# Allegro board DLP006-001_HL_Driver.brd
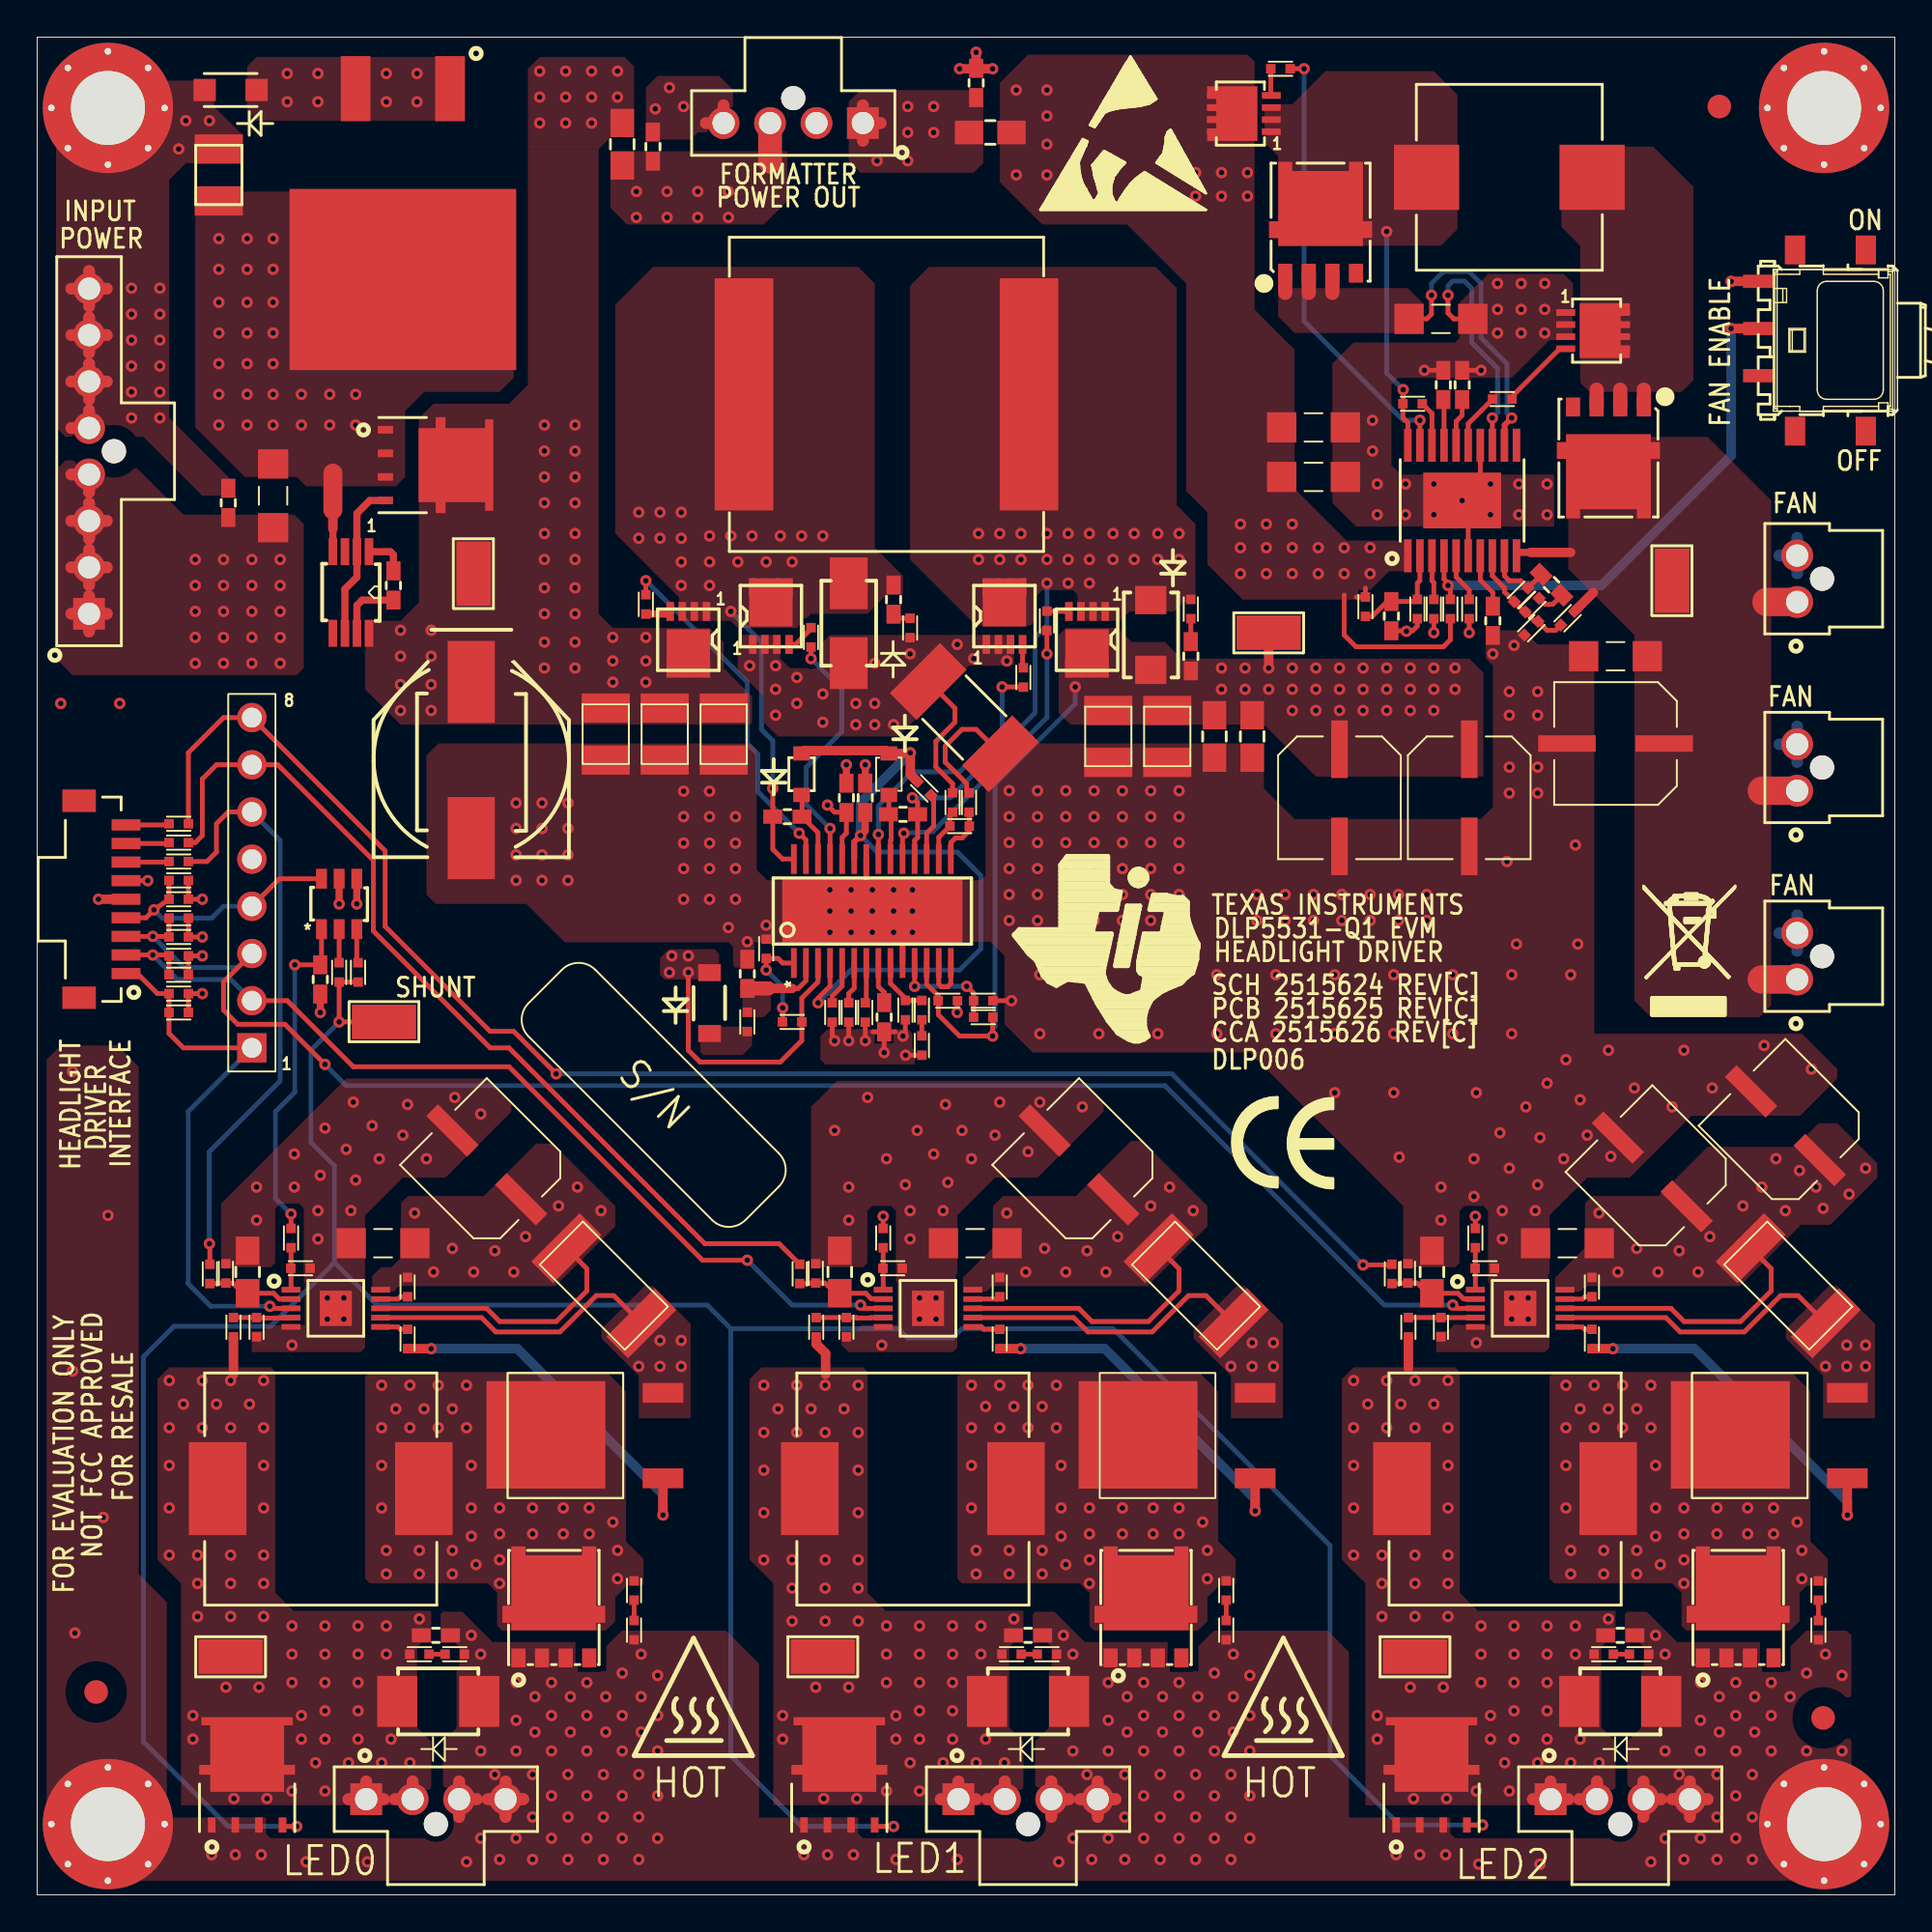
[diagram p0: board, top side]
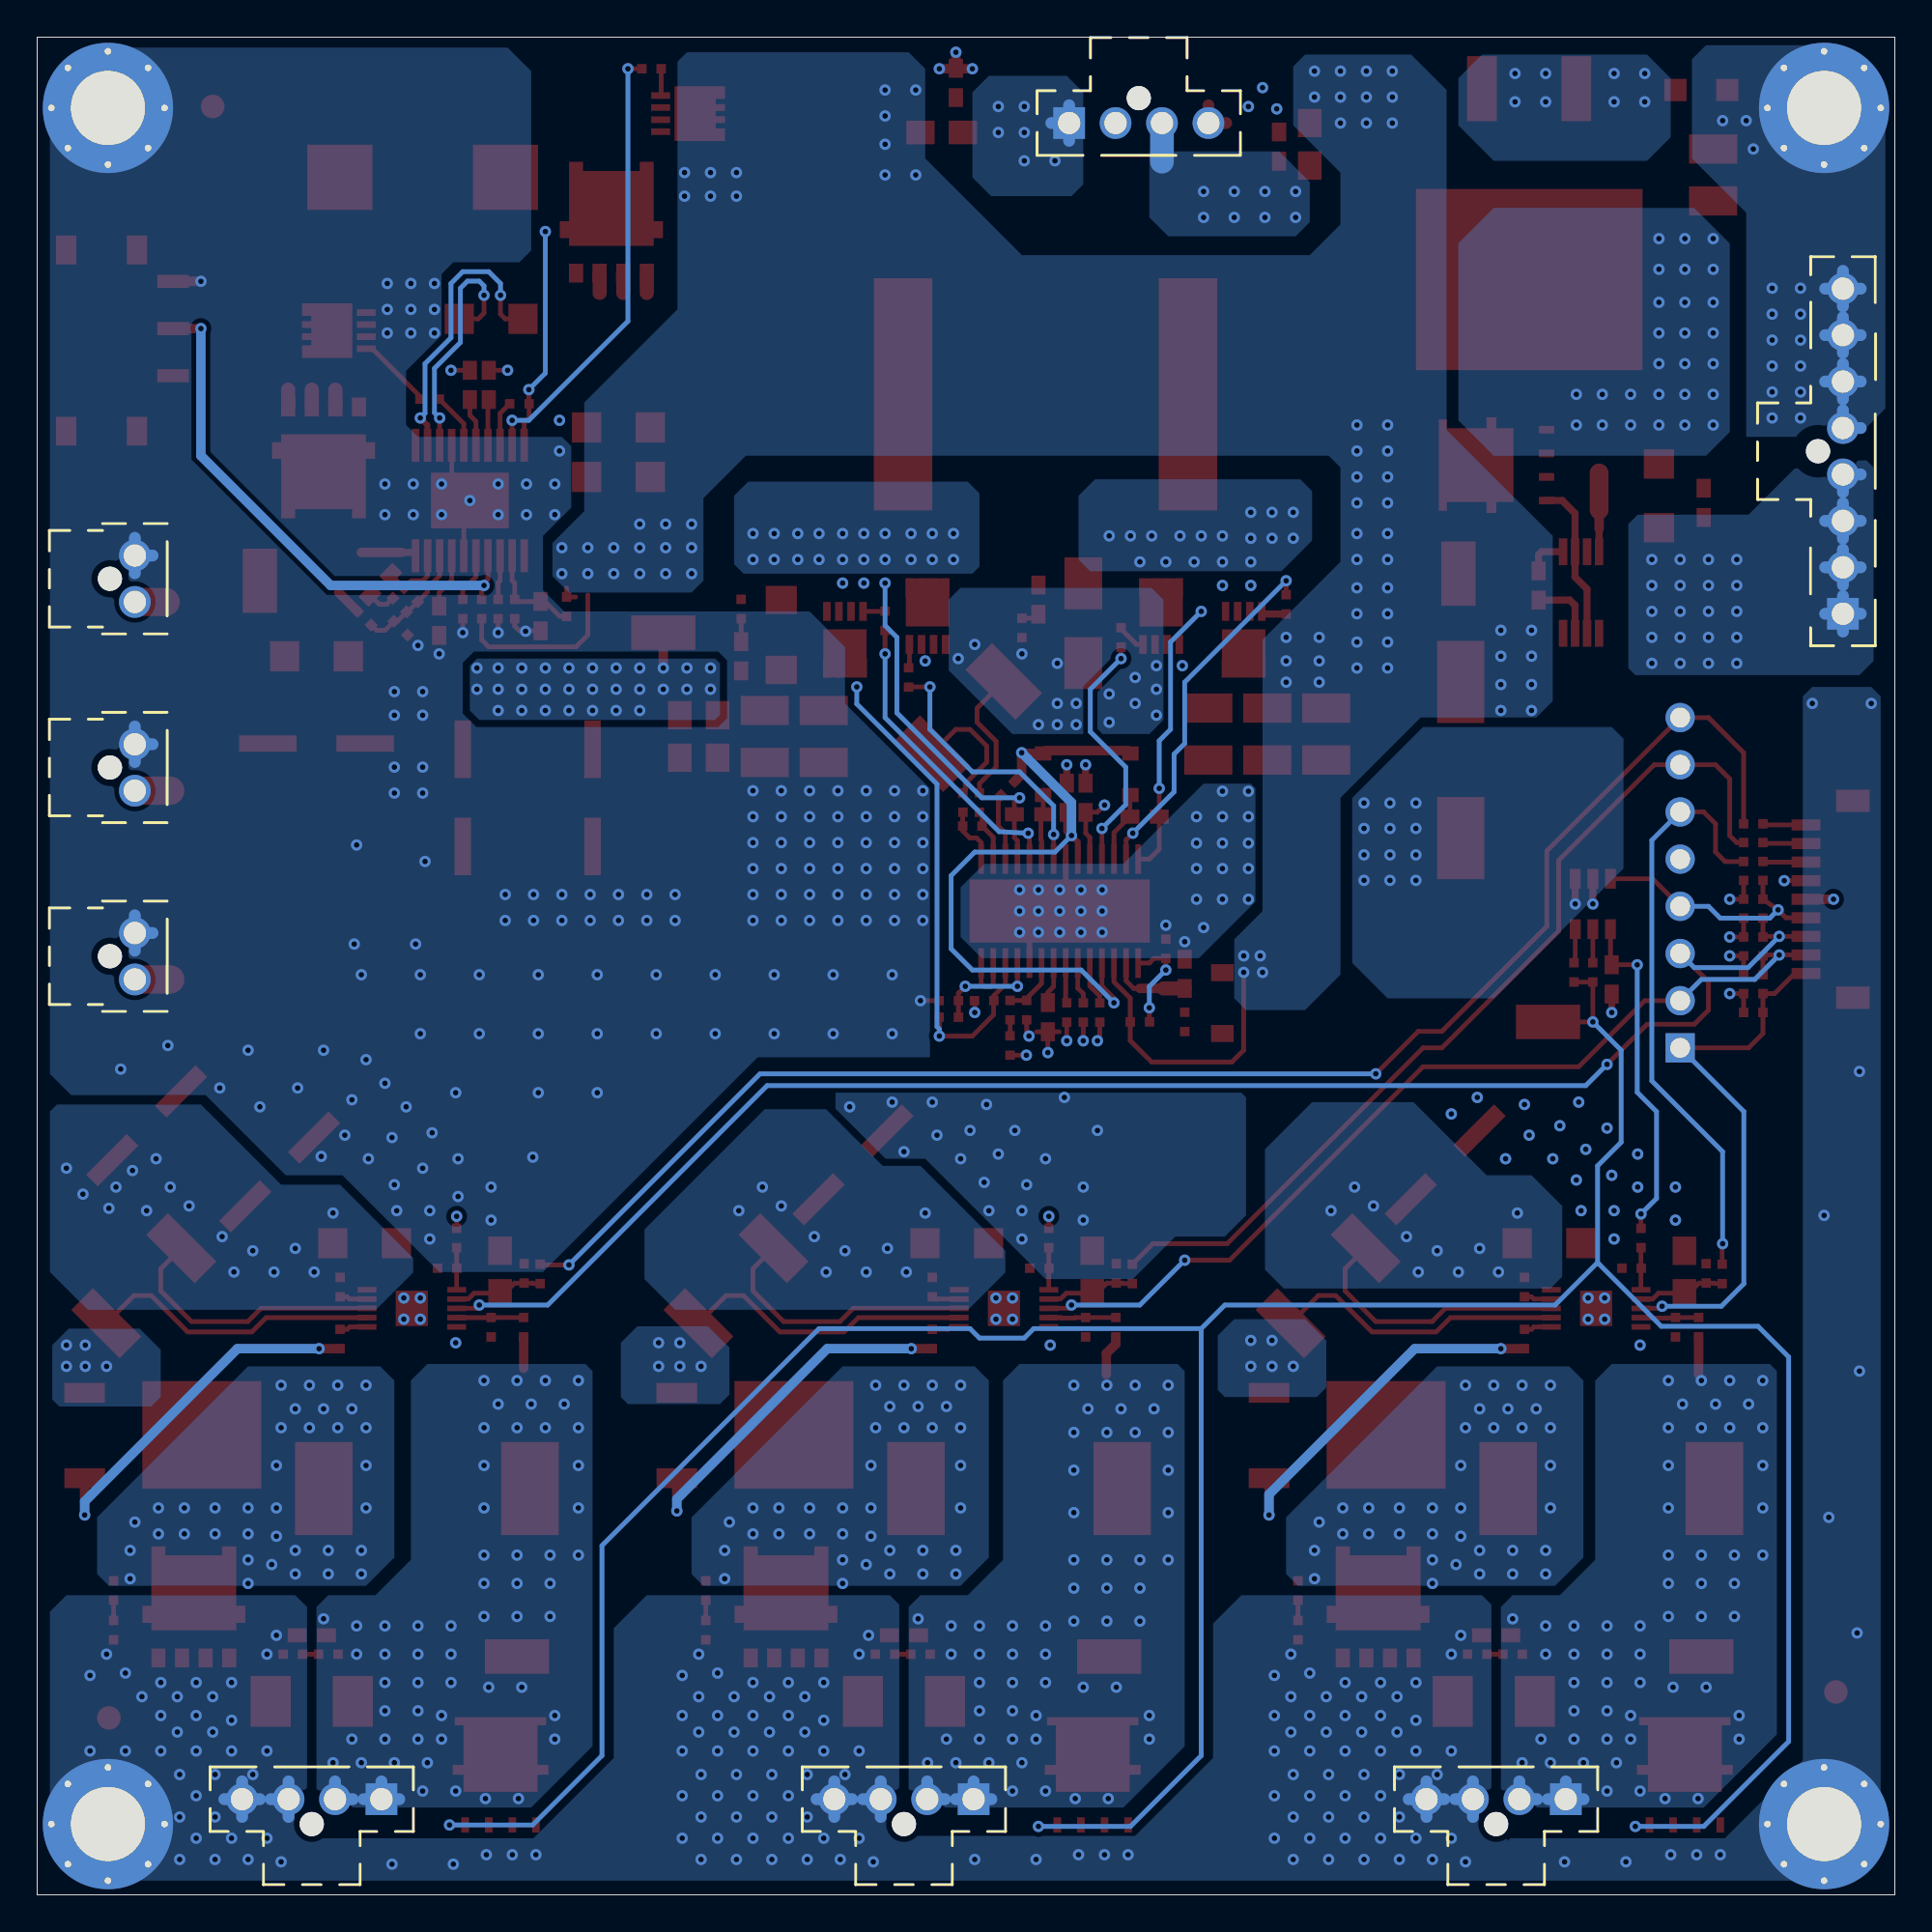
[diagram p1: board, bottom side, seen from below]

Outline 100 x 100 mm; copper layers: TOP, L2_GND, L3_PWR, BOTTOM. Coordinates in mm from the lower left corner of the outline.
Outline path: 0,100 0,0 100,0 100,100 0,100

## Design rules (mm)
net group PWR: nets CSN CSP LO P6P5V

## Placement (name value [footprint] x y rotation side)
C1  0.1uF  [C_0603]  50.55 97.54 270 top
C2  0.1uF  [C_0603]  33.15 94.11 270 top
C3  10uF  [C_1210]  9.78 92.58 270 top
C4  1uF  [C_0603]  75.69 81.28 270 top
C5  1uF  [C_0603]  76.71 81.28 270 top
C6  0.1uF  [C_0402]  74.04 80.26 0 top
C7  4.7uF  [C_1206]  68.71 78.99 180 top
C8  4.7uF  [C_1206]  68.71 76.33 180 top
C9  0.1uF  [C_0603]  10.29 74.93 270 top
C10  0.68uF  [C_0603]  81.52 70.52 315 top
C11  1uF  [C_0603]  19.18 70.48 90 top
C12  0.015uF  [C_0402]  79.88 69.98 225 top
C13  100pF  [C_0402]  62.1 69.22 270 top
C14  0.022uF  [C_0402]  74.3 69.22 90 top
C15  330pF  [C_0402]  77.09 69.22 90 top
C16  0.047uF  [C_0603]  78.36 68.58 90 top
C17  100pF  [C_0402]  46.99 68.2 90 top
C18  4.7uF  [C_1206]  84.96 66.67 0 top
C19  2.2uF  [C_1210]  30.61 62.48 90 top
C20  2.2uF  [C_1210]  33.78 62.48 90 top
C21  2.2uF  [C_1210]  36.96 62.48 90 top
C22  3.3uF  [C_0805]  63.37 62.36 90 top
C23  3.3uF  [C_0805]  65.41 62.36 90 top
C24  10uF  [C_1210]  57.66 62.36 90 top
C25  10uF  [C_1210]  60.83 62.36 90 top
C26  100uF  [CAP_ALUM_EEE-FPE101XAP]  84.96 61.98 270 top
C27  68uF  [CAL_ALUM_EEH-ZC1J680V]  23.37 61.09 270 top
C28  0.1uF  [C_0603]  43.56 59.05 270 top
C29  1uF  [C_0603]  44.58 59.05 270 top
C30  47uF  [CAP_ALUM_EEH-ZC1V470P]  70.1 59.05 0 top
C31  47uF  [CAP_ALUM_EEH-ZC1V470P]  77.09 59.05 0 top
C32  0.1uF  [C_0603]  46.61 58.17 180 top
C33  0.1uF  [C_0603]  40.39 58.04 0 top
C34  47pF  [C_0402]  49.66 57.53 180 top
C35  2200pF  [C_0402]  7.62 53.59 180 top
C36  0.1uF  [C_0603]  15.24 49.28 90 top
C37  2200pF  [C_0402]  7.62 51.56 180 top
C38  2200pF  [C_0402]  7.62 50.55 180 top
C39  0.1uF  [C_0603]  38.23 49.58 270 top
C40  2200pF  [C_0402]  7.62 48.51 180 top
C41  100pF  [C_0402]  46.74 47.62 90 top
C42  0.022uF  [C_0402]  47.62 47.62 90 top
C43  1000pF  [C_0402]  42.8 47.5 90 top
C44  100pF  [C_0402]  44.58 47.5 90 top
C45  0.1uF  [C_0603]  45.59 47.24 90 top
C46  100pF  [C_0402]  49.02 48.13 180 top
C47  100 uF  [CAP_ALUM_EEE-FK1E101SP]  94.11 41.4 225 top
C48  100 uF  [CAP_ALUM_EEE-FK1E101SP]  24.21 39.29 225 top
C49  100 uF  [CAP_ALUM_EEE-FK1E101SP]  56.08 39.29 225 top
C50  100 uF  [CAP_ALUM_EEE-FK1E101SP]  86.94 38.91 225 top
C51  4.7uF  [C_1206]  18.62 35.08 0 top
C52  4.7uF  [C_1206]  50.5 35.08 0 top
C53  4.7uF  [C_1206]  82.37 35.08 0 top
C54  10uF  [C_0805]  11.33 33.53 270 top
C55  10uF  [C_0805]  43.21 33.53 270 top
C56  10uF  [C_0805]  75.08 33.53 270 top
C57  1uF  [C_0402]  19.94 32.72 90 top
C58  1uF  [C_0402]  51.82 32.72 90 top
C59  1uF  [C_0402]  83.69 32.72 90 top
C60  2200pF  [C_0402]  11.81 30.56 90 top
C61  2200pF  [C_0402]  43.56 30.56 90 top
C62  2200pF  [C_0402]  75.56 30.56 90 top
C63  1000pF  [C_0402]  32.13 16.38 90 top
C64  1000pF  [C_0402]  64.01 16.38 90 top
C65  1000pF  [C_0402]  95.89 16.38 90 top
C66  1uF  [C_0603]  21.46 13.97 180 top
C67  1uF  [C_0603]  53.34 13.97 180 top
C68  1uF  [C_0603]  85.22 13.97 180 top
C69  0.1uF  [C_0402]  20.57 12.95 180 top
C70  0.1uF  [C_0402]  52.45 12.95 180 top
C71  0.1uF  [C_0402]  84.33 12.95 180 top
D1  PTVS17VS1UR,115  [SOD-123W_PTVS17VS1UR-115]  10.41 97.16 0 top
D2  LDP01-39AY  [D2PAK-3_LDP01-39AY]  19.68 88.52 180 top
D3  NRVTS560EMFST1G  [SO-8_NRVTS560EMFST1G]  69.09 90.04 0 top
D4  NRVTS560EMFST1G  [SO-8_NRVTS560EMFST1G]  84.58 77.34 180 top
D5  B360A-13-F  [SMA_B360A-13-F]  43.69 68.45 90 top
D6  SS12-E3/61T  [SMA-DO-214AC_SS12-E3-61T]  59.94 67.82 270 top
D7  BAT46WJ,115  [SOD-323-2_BAT46WJ-115]  41.15 60.33 270 top
D8  BAT46WJ,115  [SOD-323-2_BAT46WJ-115]  45.85 60.33 270 top
D9  MBR0520LT1G  [SOD-123_MBR0520LT1G]  36.2 48.01 90 top
D10  NTS1545MFST1G  [SO-8-FL_NTS1545MFST1G]  27.81 15.47 0 top
D11  NTS1545MFST1G  [SO-8-FL_NTS1545MFST1G]  59.69 15.47 0 top
D12  NTS1545MFST1G  [SO-8-FL_NTS1545MFST1G]  91.57 15.47 0 top
D13  B240Q-13-F  [SMB-2_B240Q-13-F]  21.59 10.41 180 top
D14  B240Q-13-F  [SMB-2_B240Q-13-F]  53.34 10.41 180 top
D15  B240Q-13-F  [SMB-2_B240Q-13-F]  85.22 10.41 180 top
H1  68000-408HLF  [HEADER_68000-408HLF]  11.56 45.59 90 top
J1  105309-1204  [CONN-4POS_105309-1204]  44.45 95.38 180 top
J2  105309-1208  [CONN-8POS_105309-1208]  2.79 68.96 90 top
J3  105309-1202  [CONN-2POS_105309-1202]  94.74 69.6 90 top
J4  105309-1202  [CONN-2POS_105309-1202]  94.74 59.44 90 top
J5  501331-0907  [CONN-9POS_501331-0907]  2.29 53.59 270 top
J6  105309-1202  [CONN-2POS_105309-1202]  94.74 49.28 90 top
J7  105309-1304  [CONN-4POS_105309-1304]  17.71 5.15 0 top
J8  105309-1304  [CONN-4POS_105309-1304]  49.59 5.15 0 top
J9  105309-1304  [CONN-4POS_105309-1304]  81.47 5.15 0 top
L1  100OHM @ 100MHZ  [L_0805]  51.31 94.87 0 top
L2  100OHM @ 100MHZ  [L_0805]  31.5 94.23 90 top
L3  33uH  [INDUCTOR_SRP1038A-330M]  79.25 92.46 0 top
L4  4.7uH  [INDUCTOR_SRP1770TA-4R7M]  45.72 80.77 0 top
L5  50OHM @ 100MHZ  [L_1206]  12.7 75.31 270 top
L6  120OHM @ 100MHZ  [L_0402]  7.62 57.66 0 top
L7  120OHM @ 100MHZ  [L_0402]  7.62 56.64 0 top
L8  120OHM @ 100MHZ  [L_0402]  7.62 55.63 0 top
L9  22uH  [INDUCTOR_SRP1265A-220M]  15.27 21.87 180 top
L10  22uH  [INDUCTOR_SRP1265A-220M]  47.14 21.87 180 top
L11  22uH  [INDUCTOR_SRP1265A-220M]  79.02 21.87 180 top
MH1  MOUNTING_HOLE  [MH9-276-157]  3.81 96.19 0 top
MH2  MOUNTING_HOLE  [MH9-276-157]  96.19 96.19 0 top
MH3  MOUNTING_HOLE  [MH9-276-157]  3.81 3.81 0 top
MH4  MOUNTING_HOLE  [MH9-276-157]  96.19 3.81 0 top
NOREF  -  []  -41.02 -60.33 0 top
NOREF#2  -  []  38.99 162.81 0 top
NOREF#3  -  [unnamed#2]  96.14 9.53 0 top
NOREF#4  -  []  88.95 51.36 0 top
NOREF#5  -  [unnamed#2]  3.17 10.92 0 top
NOREF#6  -  []  67.06 10.03 0 top
NOREF#7  -  []  0 0 90 top
NOREF#8  -  []  63.63 101.73 0 top
NOREF#9  -  [unnamed#2]  90.55 96.27 270 top
NOREF#10  -  []  0.13 112.78 0 top
NOREF#11  -  []  0 100 0 top
NOREF#12  -  []  35.31 10.03 0 top
NOREF#13  -  []  204.14 101.9 0 top
NOREF#14  -  []  100.2 113.03 0 top
NOREF#15  -  []  99.95 -13.46 0 top
Q1  BUK7M67-60EX  [LFPAK33-5_BUK7M67-60EX]  64.77 95.89 90 top
Q2  BUK7M67-60EX  [LFPAK33-5_BUK7M67-60EX]  83.95 84.2 270 top
Q3  SQJA80EP-T1_GE3  [POWERPAK-SO-8L-4_SQJA80EP]  21.46 76.96 270 top
Q4  DMT6007LFG-7  [POWERDI3333-8_DMT6007LFG-7]  39.5 68.83 90 top
Q5  DMT6007LFG-7  [POWERDI3333-8_DMT6007LFG-7]  52.07 68.83 90 top
Q6  DMT6007LFG-7  [POWERDI3333-8_DMT6007LFG-7]  35.05 67.56 270 top
Q7  DMT6007LFG-7  [POWERDI3333-8_DMT6007LFG-7]  56.52 67.56 270 top
Q8  IPD50P04P4-13  [TO-252-3_IPD50P04P4-13]  29.18 24.71 90 top
Q9  IPD50P04P4-13  [TO-252-3_IPD50P04P4-13]  61.06 24.71 90 top
Q10  IPD50P04P4-13  [TO-252-3_IPD50P04P4-13]  92.94 24.71 90 top
Q11  SQJ148EP-T1_GE3  [POWERPAK-SO-8L-4_SQJ148EP]  11.3 6.48 0 top
Q12  SQJ148EP-T1_GE3  [POWERPAK-SO-8L-4_SQJ148EP]  43.18 6.48 0 top
Q13  SQJ148EP-T1_GE3  [POWERPAK-SO-8L-4_SQJ148EP]  75.06 6.48 0 top
R1  2.4  [R_0402]  66.93 98.3 180 top
R2  50m  [R_1206]  75.56 84.84 0 top
R3  2.4  [R_0402]  78.87 80.52 0 top
R4  10  [R_0603]  46.1 69.72 270 top
R5  2.4  [R_0402]  32.77 69.47 270 top
R6  1.1k  [R_0402]  80.48 69.43 45 top
R7  75k  [R_0402]  71.5 69.34 270 top
R8  13k  [R_0402]  75.18 69.22 270 top
R9  10k  [R_0402]  76.07 69.22 90 top
R10  22.1k  [R_0603]  72.9 68.83 270 top
R11  2.67k  [R_0402]  82.39 68.72 225 top
R12  2.4  [R_0402]  54.36 68.58 90 top
R13  300  [R_0402]  80.43 68.18 225 top
R14  2.4  [R_0402]  41.66 67.69 90 top
R15  10  [R_0603]  62.1 66.67 90 top
R16  2.4  [R_0402]  53.09 65.53 90 top
R17  8m  [KOA_TLRH3APTTE8L00F]  49.91 63.37 315 top
R18  10k  [R_0402]  47.75 59.56 315 top
R20  100  [R_0402]  49.28 58.8 90 top
R21  100  [R_0402]  50.16 58.8 90 top
R22  10k  [R_0402]  7.62 54.61 0 top
R23  2.4  [R_0402]  16.26 49.66 270 top
R24  2.4  [R_0402]  17.27 49.66 270 top
R25  10k  [R_0402]  7.62 52.58 0 top
R26  59k  [R_0402]  39.24 50.93 90 top
R27  10k  [R_0402]  7.62 49.53 0 top
R28  10k  [R_0402]  7.62 47.5 0 top
R31  61.9k  [R_0402]  43.69 47.5 270 top
R32  19.6k  [R_0402]  50.93 48.13 0 top
R33  374k  [R_0402]  50.93 47.24 180 top
R34  10  [R_0402]  38.23 46.99 270 top
R35  249k  [R_0402]  40.64 46.99 180 top
R36  10k  [R_0402]  47.62 45.72 270 top
R38  49.9k  [R_0402]  13.67 35.36 90 top
R39  49.9k  [R_0402]  45.54 35.36 90 top
R40  49.9k  [R_0402]  77.42 35.36 90 top
R41  5.76k  [R_0402]  14.17 33.73 180 top
R42  5.76k  [R_0402]  46.05 33.73 180 top
R43  5.76k  [R_0402]  77.93 33.73 180 top
R44  10.2k  [R_0402]  10.16 33.45 270 top
R45  10.2k  [R_0402]  41.91 33.45 270 top
R46  10.2k  [R_0402]  73.79 33.45 270 top
R47  16.9k  [R_0402]  9.3 33.43 270 top
R48  16.9k  [R_0402]  41.05 33.43 270 top
R49  16.9k  [R_0402]  72.92 33.43 270 top
R50  30m  [R_2512]  30.51 32.79 135 top
R51  30m  [R_2512]  62.38 32.79 135 top
R52  30m  [R_2512]  94.26 32.79 135 top
R53  3.3k  [R_0402]  10.57 30.56 270 top
R54  3.3k  [R_0402]  41.94 30.56 270 top
R55  3.3k  [R_0402]  73.81 30.56 270 top
R56  0  [R_0402]  19.94 29.92 270 top
R57  0  [R_0402]  51.82 29.92 270 top
R58  0  [R_0402]  83.69 29.92 270 top
R59  1  [R_0402]  32.13 14.25 90 top
R60  1  [R_0402]  64.01 14.25 90 top
R61  1  [R_0402]  95.89 14.25 90 top
R62  1  [R_0402]  22.48 12.95 180 top
R63  1  [R_0402]  54.36 12.95 180 top
R64  1  [R_0402]  86.23 12.95 180 top
SW1  G3T12AH-R  [SWITCH_G3T12AH-R]  96.52 83.69 90 top
TP1  Probe-Testpoint  [TESTPOINT_S1751-46R]  23.5 71.12 90 top
TP2  Probe-Testpoint  [TESTPOINT_S1751-46R]  88.01 70.74 90 top
TP3  Probe-Testpoint  [TESTPOINT_S1751-46R]  66.29 67.94 180 top
TP4  Probe-Testpoint  [TESTPOINT_S1751-46R]  18.67 46.99 0 top
TP5  Probe-Testpoint  [TESTPOINT_S1751-46R]  10.41 12.83 180 top
TP6  Probe-Testpoint  [TESTPOINT_S1751-46R]  42.29 12.83 180 top
TP7  Probe-Testpoint  [TESTPOINT_S1751-46R]  74.17 12.83 180 top
U1  LM25118Q1MHE-NOPB  [HTSSOP-20_LM25118Q1MHE-NOPB]  76.71 75.06 90 top
U2  LM74610-Q1  [VSSOP-8_LM74610QDGKTQ1]  16.89 70.1 180 top
U3  UCC27511A-Q1  [SOT-23_UCC27511A-Q1]  16.26 53.34 0 top
U4  LM5175-Q1  [HTSSOP-28_LM5175QPWPTQ1]  44.96 52.96 90 top
U5  LM3409-Q1  [MSOP-10-POWERPAD_LM3409QMY-NOPB]  16.08 31.57 0 top
U6  LM3409-Q1  [MSOP-10-POWERPAD_LM3409QMY-NOPB]  47.96 31.57 0 top
U7  LM3409-Q1  [MSOP-10-POWERPAD_LM3409QMY-NOPB]  79.83 31.57 0 top

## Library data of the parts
C1 C2 C4-C18 C22 C23 C28 C29 C32-C46 C51-C71 = CAP_NP_dsize
C3 C19-C21 C24 C25 = CAP_NP_dsize: Tolerance: TOL
C26 C27 C30 C31 C47-C50 = CAP_POL_dsize
D1 = DIODE ZENER
D2 = DIODE ZENER_0
D3 D4 = DIODE_SCHOTTKY_dsize_12
D5 = DIODE_SCHOTTKY_dsize: User Part Number: C
D6-D9 D13-D15 = DIODE_SCHOTTKY_dsize
D10-D12 = DIODE_SCHOTTKY_dsize_8
H1 = HEADER_1X8_H_dsize_0
J1 J7-J9 = CONN_1X4PINS_dsize
J2 = CONN_1X6PINS_dsize_0
J3 J4 J6 = CONN_1X4PINS_dsize_2
J5 = CONN_1X9PINS_dsize
L1 L2 = FERRITE_L
L3 L4 L9-L11 = L
L5 = FERRITE_L_1
L6-L8 = FERRITE_L_0
MH1-MH4 = MOUNTING_HOLES_9_DSIZE_0
Q1 Q2 Q4-Q7 = NFET-DMN4800_3
Q3 = NFET-DMN4800_5
Q8-Q10 = PFET-POWERD-TSOP6_6
Q11-Q13 = NFET-DMN4800_4
R1-R18 R20-R28 R31-R36 R38-R64 = RESISTOR_dsize
SW1 = SW_SPST_1_dsize_5
TP1-TP7 = Testpoint_0
U1 = LM25118Q1MHE/NOPB_4
U2 = LM3409_SSOP_3
U3 = LM3409_SSOP_6
U4 = LM25118Q1MHE/NOPB_5
U5-U7 = LM3409_SSOP_2

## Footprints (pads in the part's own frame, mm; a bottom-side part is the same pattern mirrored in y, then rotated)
C_0402
  rect 0.508x0.508 smd: 1(-0.521,0) 2(0.521,0)
C_0603
  rect 1.016x0.762 smd: 1(-0.787,0) 2(0.787,0)
C_0805
  rect 1.524x1.27 smd: 1(-1.143,0) 2(1.143,0)
C_1206
  rect 1.575x1.626 smd: 1(-1.714,0) 2(1.714,0)
C_1210
  rect 1.575x2.591 smd: 1(-1.397,0) 2(1.397,0)
CAL_ALUM_EEH-ZC1J680V
  rect 4.42x2.54 smd: 1(-4.204,0) 2(4.204,0)
CAP_ALUM_EEE-FK1E101SP
  rect 0.889x3.099 smd: 1(0,2.616) 2(0,-2.616)
CAP_ALUM_EEE-FPE101XAP
  rect 0.889x3.099 smd: 1(0,2.616) 2(0,-2.616)
CAP_ALUM_EEH-ZC1V470P
  rect 0.889x3.099 smd: 1(0,2.616) 2(0,-2.616)
CONN-2POS_105309-1202
  round 1.3 hole 1.3 unplated: (1.25,-1.34)
  round 1.708 hole 1.2: 1(0,0) 2(2.5,0)
CONN-4POS_105309-1204
  round 1.3 hole 1.3 unplated: (3.75,-1.34)
  rect 1.708x1.708 hole 1.2: 1(0,0)
  round 1.708 hole 1.2: 2(2.5,0) 3(5,0) 4(7.5,0)
CONN-4POS_105309-1304
  round 1.3 hole 1.3 unplated: (3.75,-1.34)
  rect 1.708x1.708 hole 1.2: 1(0,0)
  round 1.708 hole 1.2: 2(2.5,0) 3(5,0) 4(7.5,0)
CONN-8POS_105309-1208
  round 1.3 hole 1.3 unplated: (8.75,-1.34)
  rect 1.708x1.708 hole 1.2: 1(0,0)
  round 1.708 hole 1.2: 2(2.5,0) 3(5,0) 4(7.5,0) 5(10,0) 6(12.5,0) 7(15,0) 8(17.5,0)
CONN-9POS_501331-0907
  rect 1.2x1.8 smd: (-5.3,-0.027) (5.3,-0.027)
  rect 0.6x1.55 smd: 1(4,2.498) 2(3,2.498) 3(2,2.498) 4(1,2.498) 5(0,2.498) 6(-1,2.498) 7(-2,2.498) 8(-3,2.498) 9(-4,2.498)
D2PAK-3_LDP01-39AY
  rect 12.2x9.75 smd: 1(0,1.566)
  rect 1.6x3.5 smd: 2(-2.54,-8.709) 3(2.54,-8.709)
HEADER_68000-408HLF
  rect 1.575x1.575 hole 1.067: 1(0,0)
  round 1.575 hole 1.067: 2(2.54,0) 3(5.08,0) 4(7.62,0) 5(10.16,0) 6(12.7,0) 7(15.24,0) 8(17.78,0)
HTSSOP-20_LM25118Q1MHE-NOPB
  rect 1.778x0.406 smd: 1(-2.974,2.925) 2(-2.974,2.275) 3(-2.974,1.625) 4(-2.974,0.975) 5(-2.974,0.325) 6(-2.974,-0.325) 7(-2.974,-0.975) 8(-2.974,-1.625) 9(-2.974,-2.275) 10(-2.974,-2.925) 11(2.974,-2.925) 12(2.974,-2.275) 13(2.974,-1.625) 14(2.974,-0.975) 15(2.974,-0.325) 16(2.974,0.325) 17(2.974,0.975) 18(2.974,1.625) 19(2.974,2.275) 20(2.974,2.925)
  rect 2.997x4.191 smd: 21(0,0)
HTSSOP-28_LM5175QPWPTQ1
  rect 1.6x0.305 smd: 1(-2.8,4.225) 2(-2.8,3.575) 3(-2.8,2.925) 4(-2.8,2.275) 5(-2.8,1.625) 6(-2.8,0.975) 7(-2.8,0.325) 8(-2.8,-0.325) 9(-2.8,-0.975) 10(-2.8,-1.625) 11(-2.8,-2.275) 12(-2.8,-2.925) 13(-2.8,-3.575) 14(-2.8,-4.225) 15(2.8,-4.225) 16(2.8,-3.575) 17(2.8,-2.925) 18(2.8,-2.275) 19(2.8,-1.625) 20(2.8,-0.975) 21(2.8,-0.325) 22(2.8,0.325) 23(2.8,0.975) 24(2.8,1.625) 25(2.8,2.275) 26(2.8,2.925) 27(2.8,3.575) 28(2.8,4.225)
  rect 3.404x9.703 smd: 29(0,0)
INDUCTOR_SRP1038A-330M
  rect 3.505x3.505 smd: 1(-4.458,0) 2(4.458,0)
INDUCTOR_SRP1265A-220M
  rect 3.099x5.004 smd: 1(-5.55,0) 2(5.55,0)
INDUCTOR_SRP1770TA-4R7M
  rect 3.15x12.497 smd: 1(-7.671,0) 2(7.671,0)
KOA_TLRH3APTTE8L00F
  rect 2.032x3.81 smd: 1(-2.75,0) 2(2.75,0)
L_0402
  rect 0.508x0.508 smd: 1(-0.521,0) 2(0.521,0)
L_0805
  rect 1.524x1.27 smd: 1(-1.143,0) 2(1.143,0)
L_1206
  rect 1.575x1.626 smd: 1(-1.714,0) 2(1.714,0)
LFPAK33-5_BUK7M67-60EX
  rect 0.356x1.016 smd: 1(-0.975,-1.665) 2(-0.325,-1.665) 3(0.325,-1.665) 4(0.975,-1.665)
  rect 0.356x0.762 smd: 5(0.975,1.411) 6(0.325,1.411) 7(-0.325,1.411) 8(-0.975,1.411)
MH9-276-157
  round 7.01 hole 3.988: 1(0,0)
  round 0.762 hole 0.356: 2(0,3.048) 3(2.159,2.159) 4(3.048,0) 5(2.159,-2.159) 6(0,-3.048) 7(-2.159,-2.159) 8(-3.048,0) 9(-2.159,2.159)
MSOP-10-POWERPAD_LM3409QMY-NOPB
  rect 1.016x0.305 smd: 1(-2.411,1) 2(-2.411,0.5) 3(-2.411,0) 4(-2.411,-0.5) 5(-2.411,-1) 6(2.411,-1) 7(2.411,-0.5) 8(2.411,0) 9(2.411,0.5) 10(2.411,1)
  rect 1.727x1.905 smd: 11(0,0)
POWERDI3333-8_DMT6007LFG-7
  rect 1.016x0.406 smd: 1(-1.524,0.975) 2(-1.524,0.325) 3(-1.524,-0.325) 4(-1.524,-0.975) 5(1.524,-0.975) 6(1.524,-0.325) 7(1.524,0.325) 8(1.524,0.975)
POWERPAK-SO-8L-4_SQJ148EP
  rect 0.41x0.82 smd: 1(-1.905,-2.716) 2(-0.635,-2.716) 3(0.635,-2.716) 4(1.905,-2.716)
  rect 0.254x0.254 smd: 5(0,0.254)
POWERPAK-SO-8L-4_SQJA80EP
  rect 0.41x0.82 smd: 1(-1.905,-2.716) 2(-0.635,-2.716) 3(0.635,-2.716) 4(1.905,-2.716)
  rect 0.254x0.254 smd: 5(0,0.254)
R_0402
  rect 0.508x0.508 smd: 1(-0.521,0) 2(0.521,0)
R_0603
  rect 1.016x0.762 smd: 1(-0.787,0) 2(0.787,0)
R_1206
  rect 1.575x1.626 smd: 1(-1.714,0) 2(1.714,0)
R_2512
  rect 1.651x3.683 smd: 1(-2.858,0) 2(2.858,0)
SMA-DO-214AC_SS12-E3-61T
  rect 1.524x1.676 smd: A(-1.88,0) C(1.88,0)
SMA_B360A-13-F
  rect 2.794x2.032 smd: A(-2.146,0) C(2.146,0)
SMB-2_B240Q-13-F
  rect 2.159x2.743 smd: A(-2.21,0) C(2.21,0)
SO-8-FL_NTS1545MFST1G
  rect 0.762x1.016 smd: 1(-1.905,-2.716) 2(-0.635,-2.716) 3(0.635,-2.716) 4(1.905,-2.716)
  custom 1.13x1.13 smd: 5(0,1.03)
  round 0.127 smd: 6(0,0)
SO-8_NRVTS560EMFST1G
  rect 0.762x1.016 smd: 1(-1.905,-2.748) 2(-0.635,-2.748) 3(0.635,-2.748) 4(1.905,-2.748)
  rect 0.254x0.254 smd: 5(-0.508,1.016) 6(0.508,1.016)
SOD-123_MBR0520LT1G
  rect 0.914x1.219 smd: A(1.638,0) C(-1.638,0)
SOD-123W_PTVS17VS1UR-115
  rect 1.194x1.194 smd: 1(-1.397,0) 2(1.397,0)
SOD-323-2_BAT46WJ-115
  rect 0.762x0.889 smd: A(-1.118,0) C(1.118,0)
SOT-23_UCC27511A-Q1
  rect 0.584x1.067 smd: 1(-0.95,-1.356) 2(0,-1.356) 3(0.95,-1.356) 4(0.95,1.356) 5(0,1.356) 6(-0.95,1.356)
SWITCH_G3T12AH-R
  rect 1.549x1.092 smd: (-4.902,1.892) (-4.902,-1.918) (4.851,1.892) (4.851,-1.918)
  rect 0.711x1.702 smd: 4(-1.918,3.835) 5(0.622,3.835) 6(3.162,3.835)
TESTPOINT_S1751-46R
  rect 3.454x1.854 smd: 1(0,0)
TO-252-3_IPD50P04P4-13
  rect 1.067x2.184 smd: 1(-2.29,-4.504) 3(2.31,-4.504)
  round 0.102 smd: 2(0,0)
  rect 5.791x6.401 smd: TAB(0.046,1.796)
unnamed#2
  round 1.27 smd: 1(0,0)
VSSOP-8_LM74610QDGKTQ1
  rect 0.457x1.448 smd: 1(-0.972,-2.197) 2(-0.324,-2.197) 3(0.324,-2.197) 4(0.972,-2.197) 5(0.972,2.197) 6(0.324,2.197) 7(-0.324,2.197) 8(-0.972,2.197)

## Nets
16V_REG: C22.2 C23.2 C24.2 C25.2 C28.2 C30.1 C31.1 C36.2 C46.2 C47.1 C48.1 C49.1 C50.1 C51.2 C52.2 C53.2 C57.2 C58.2 C59.2 D6.C(CATHODE) Q7.5(D1) Q7.6(D2) Q7.7(D3) Q7.8(D4) R15.1 R33.1 R38.2 R39.2 R40.2 R50.2 R51.2 R52.2 TP3.1(TP) U3.1(VDD) U4.12(VOSNS) U4.24(BIAS) U5.8(CSP) U5.10(VIN) U6.8(CSP) U6.10(VIN) U7.8(CSP) U7.10(VIN)
GND_SIGNAL: C1.1 C2.1 C3.1 C4.1 C5.1 C7.1 C8.1 C9.1 C14.1 C15.1 C16.1 C18.1 C19.1 C20.1 C21.1 C22.1 C23.1 C24.1 C25.1 C26.2 C27.2 C28.1 C29.1 C30.2 C31.2 C35.1 C36.1 C37.1 C38.1 C39.1 C40.1 C41.1 C43.1 C44.1 C45.1 C46.1 C47.2 C48.2 C49.2 C50.2 C51.1 C52.1 C53.1 C54.1 C55.1 C56.1 C60.1 C61.1 C62.1 C66.1 C67.1 C68.1 D1.1(CATHODE) D10.1(A1) D10.2(A2) D10.3(A3) D11.1(A1) D11.2(A2) D11.3(A3) D12.1(A1) D12.2(A2) D12.3(A3) D13.A(ANODE) D14.A(ANODE) D15.A(ANODE) H1.5 J1.2 J1.4 J2.5 J2.6 J2.7 J2.8 J3.2 J4.2 J5.6 J6.2 J7.3 J7.4 J8.3 J8.4 J9.3 J9.4 MH1.1(HOLE) MH1.2(VIA1) MH1.3(VIA2) MH1.4(VIA3) MH1.5(VIA4) MH1.6(VIA5) MH1.7(VIA6) MH1.8(VIA7) MH1.9(VIA8) MH2.1(HOLE) MH2.2(VIA1) MH2.3(VIA2) MH2.4(VIA3) MH2.5(VIA4) MH2.6(VIA5) MH2.7(VIA6) MH2.8(VIA7) MH2.9(VIA8) MH3.1(HOLE) MH3.2(VIA1) MH3.3(VIA2) MH3.4(VIA3) MH3.5(VIA4) MH3.6(VIA5) MH3.7(VIA6) MH3.8(VIA7) MH3.9(VIA8) MH4.1(HOLE) MH4.2(VIA1) MH4.3(VIA2) MH4.4(VIA3) MH4.5(VIA4) MH4.6(VIA5) MH4.7(VIA6) MH4.8(VIA7) MH4.9(VIA8) Q2.1(S1) Q2.2(S2) Q2.3(S3) Q11.1(S1) Q11.2(S2) Q11.3(S3) Q12.1(S1) Q12.2(S2) Q12.3(S3) Q13.1(S1) Q13.2(S2) Q13.3(S3) R2.2 R8.2 R10.2 R13.2 R17.2 R21.2 R22.2 R25.2 R26.2 R27.2 R28.2 R31.2 R32.2 R36.2 R41.1 R42.1 R43.1 R44.1 R45.1 R46.1 R59.1 R60.1 R61.1 R62.1 R63.1 R64.1 SW1.6(SW0) U1.6(AGND) U1.13(CSG) U1.14(PGND) U1.21(DAP) U3.4(GND) U3.5(IN-) U4.10(AGND) U4.22(PGND) U4.29(PP) U5.5(GND) U5.11(TP) U6.5(GND) U6.11(TP) U7.5(GND) U7.11(TP)
VBATT: C9.2 J2.1 J2.2 J2.3 J2.4 L5.2
VCC: C29.2 D7.A(ANODE) D8.A(ANODE) R18.1 U4.4(MODE) U4.23(VCC)
VIN_HEATER: C1.2 J1.1 L1.1
VIN_MAIN: C2.2 J1.3 L2.1
CSN: C34.1 R21.1 U4.15(CSG)
CSP: C34.2 R20.1 U4.16(CS)
FB: R32.1 R33.2 U4.11(FB)
HDRV1: R5.1 U4.27(HDRV1)
HDRV2: R12.1 U4.19(HDRV2)
LDRV1: R14.1 U4.25(LDRV1)
LDRV2: R16.1 U4.21(LDRV2)
LO: R3.1 U1.15(LO)
P6P5V: J5.5
PMIC_LEDSEL_0: C40.2 H1.1 J5.1 R28.1 U5.3(EN)
PMIC_LEDSEL_1: C38.2 H1.2 J5.2 R27.1 U6.3(EN)
PMIC_LEDSEL_2: C37.2 H1.3 J5.3 R25.1 U7.3(EN)
PMIC_LEDSEL_3: C35.2 H1.4 J5.4 R22.1 U3.6(IN+)
PWM0_OUT_F: H1.6 L8.2 R47.1
PWM1_OUT_F: H1.7 L7.2 R48.1
PWM2_OUT_F: H1.8 L6.2 R49.1
SHUNT_EN: Q11.4(G) Q12.4(G) Q13.4(G) R23.2 R24.2 TP4.1(TP)
SW1: C33.1 D5.C(CATHODE) L4.1 Q4.5(D1) Q4.6(D2) Q4.7(D3) Q4.8(D4) Q6.1(S1) Q6.2(S2) Q6.3(S3) R4.1 U4.28(SW1)
SW2: C13.1 C32.1 D6.A(ANODE) L4.2 Q5.5(D1) Q5.6(D2) Q5.7(D3) Q5.8(D4) Q7.1(S1) Q7.2(S2) Q7.3(S3) U4.18(SW2)
V_BATT_PROT: C7.2 C8.2 C19.2 C20.2 C21.2 C27.1 D9.A(ANODE) L1.2 L2.2 Q1.5(D1) Q1.6(D2) Q1.7(D3) Q1.8(D4) Q3.5 Q6.5(D1) Q6.6(D2) Q6.7(D3) Q6.8(D4) R7.1 R9.1 R35.1 TP1.1(TP) U1.1(VIN) U2.8(CATHODE) U4.3(VISNS)
V_FAN: C18.2 C26.1 D4.5(CATHODE5) D4.6(CATHODE6) J3.1 J4.1 J6.1 R11.1 TP2.1(TP) U1.10(VOUT)
V_LED_0: C68.2 C71.2 D15.C(CATHODE) J9.1 J9.2 L11.2 Q13.5(D) R55.2 TP7.1(TP)
V_LED_1: C66.2 C69.2 D13.C(CATHODE) J7.1 J7.2 L9.2 Q11.5(D) R53.2 TP5.1(TP)
V_LED_2: C67.2 C70.2 D14.C(CATHODE) J8.1 J8.2 L10.2 Q12.5(D) R54.2 TP6.1(TP)
N56946: R38.1 R41.2 U5.1(UVLO)
N57442: C60.2 R53.1 U5.4(COFF)
N57562: C57.1 U5.9(VCC)
N57763: Q8.3(S) R50.1 U5.7(CSN)
N57852: R56.1 U5.6(PGATE)
N60750: R39.1 R42.2 U6.1(UVLO)
N60866: C61.2 R54.1 U6.4(COFF)
N60906: C58.1 U6.9(VCC)
N60948: Q9.3(S) R51.1 U6.7(CSN)
N61008: R57.1 U6.6(PGATE)
N64164: R40.1 R43.2 U7.1(UVLO)
N64276: C62.2 R55.1 U7.4(COFF)
N64324: C59.1 U7.9(VCC)
N64418: Q10.3(S) R52.1 U7.7(CSN)
N64426: R58.1 U7.6(PGATE)
N66768: C39.2 R34.1 U4.2(VIN)
N66777: D9.C(CATHODE) R34.2
N67488: C44.2 U4.7(SLOPE)
N67495: C43.2 U4.5(DITH)
N67553: R26.1 R35.2 U4.1(EN / UVLO)
N67657: R18.2 U4.17(PGOOD)
N68022: C41.2 C42.2 U4.9(COMP)
N68052: C42.1 R36.1
N68109: R31.1 U4.6(RT / SYNC)
N68463: C33.2 D7.C(CATHODE) U4.26(BOOT1)
N68698: C32.2 D8.C(CATHODE) U4.20(BOOT2)
N69433: Q6.4(G) R5.2
N70256: Q4.4(G) R14.2
N70284: C17.1 D5.A(ANODE) Q4.1(S1) Q4.2(S2) Q4.3(S3) Q5.1(S1) Q5.2(S2) Q5.3(S3) R17.1 R20.2
N70639: Q7.4(G) R12.2
N70965: C17.2 R4.2
N71936: C13.2 R15.2
N87249: C14.2 R7.2 R10.1 U1.2(UVLO)
N87366: C16.2 U1.7(SS)
N87373: C15.2 U1.5(RAMP)
N87380: R8.1 U1.3(RT)
N87387: C5.2 U1.16(VCC)
N87394: C4.2 U1.17(VCCX)
N87932: C6.1 D3.5(CATHODE5) D3.6(CATHODE6) L3.1 Q1.1(S1) Q1.2(S2) Q1.3(S3) U1.20(HS)
N88013: R1.1 U1.19(HO)
N88019: C6.2 U1.18(HB)
N88053: D3.1(ANODE1) D3.2(ANODE2) D3.3(ANODE3) R2.1 U1.12(CS)
N88776: D4.1(ANODE1) D4.2(ANODE2) D4.3(ANODE3) L3.2 Q2.5(D1) Q2.6(D2) Q2.7(D3) Q2.8(D4)
N88824: Q2.4(G) R3.2
N88961: C12.2 R6.1 R11.2 R13.1 U1.8(FB)
N89225: C10.1 C12.1 U1.9(COMP)
N89343: C10.2 R6.2
N14686613: Q5.4(G) R16.2
N14713667: Q3.4(G) U2.2(GATE PULL DOWN) U2.6(GATE DRIVE)
N14713719: C3.2 D2.1(CATHODE) L5.1 Q3.1(S1) Q3.2(S2) Q3.3(S3) U2.4(ANODE)
N14713759: C11.1 U2.7(VCAPH)
N14725098: C54.2 R44.2 R47.2 U5.2(IADJ)
N14726673: C55.2 R45.2 R48.2 U6.2(IADJ)
N14726919: C56.2 R46.2 R49.2 U7.2(IADJ)
N14728608: C63.2 D10.5(C5) D10.6(C6) L9.1 Q8.2(D2) Q8.TAB(D1)
N14729090: C64.2 D11.5(C5) D11.6(C6) L10.1 Q9.2(D2) Q9.TAB(D1)
N14729291: C65.2 D12.5(C5) D12.6(C6) L11.1 Q10.2(D2) Q10.TAB(D1)
N14733774: R24.1 U3.3(OUTL)
N14733778: R23.1 U3.2(OUTH)
N14755460: C11.2 U2.1(VCAPL)
N14772112: D1.2(ANODE) D2.2(ANODE1) D2.3(ANODE2)
N14778799: R9.2 SW1.5(COMM) U1.4(EN)
N14789264: C65.1 R61.2
N14790575: C63.1 R59.2
N14791153: C64.1 R60.2
N14801227: C71.1 R64.2
N14802192: U4.13(ISNS(-)) U4.14(ISNS(+))
N14805188: Q10.1(G) R58.2
N14810522: Q9.1(G) R57.2
N14810532: Q8.1(G) R56.2
N14814395: C70.1 R63.2
N14818963: J5.7 L8.1
N14818967: J5.8 L7.1
N14818971: J5.9 L6.1
N14901904: C69.1 R62.2
N15037743: C45.2 U4.8(SS)
N15077521: Q1.4(G) R1.2

Pads without a net: D3 4; D4 4; D10 4; D11 4; D12 4; NOREF#3 1; NOREF#5 1; NOREF#9 1; SW1 4; U1 11; U2 3 5

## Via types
v1: diameter 0.61, hole 0.305, TOP to BOTTOM, 1064 vias

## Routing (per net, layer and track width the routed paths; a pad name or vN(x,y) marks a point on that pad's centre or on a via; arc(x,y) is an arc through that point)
16V_REG: length 97.9
  TOP w0.254: U6.8 56.07,31.57 56.78,30.86 59.82,30.86 61.47,32.51 61.47,33.71 R51.2 ; R52.2 93.34,33.71 93.34,32.51 91.69,30.86 88.66,30.86 87.95,31.57 U7.8 ; R39.2 v1(45.54,36.53) ; R33.1 51.44,47.23 v1(51.44,46.23) 49.66,46.23 48.51,47.37 48.51,48.12 C46.2 48.5,48.4 47.88,49.02 47.88,50.16 U4.12 ; U5.8 24.19,31.57 24.9,30.86 27.94,30.86 29.59,32.51 29.59,33.71 R50.2 ; R40.2 v1(77.42,36.53) ; v1(13.87,50.06) C36.2 15.31,50.13 U3.1 ; v1(42.55,58.66) 42.93,58.28 43.55,58.28 C28.2 43.56,57.15 43.33,56.92 U4.24 ; R38.2 v1(13.67,36.65)
  TOP w0.508: TP3.1 v1(66.29,66.04)
  BOTTOM w0.254: v1(13.67,36.65) 12.83,37.49 12.83,42.16 13.87,43.21 v1(13.87,50.06) ; v1(51.44,46.23) 51.44,46.61 51.56,46.74 51.56,59.79 55.88,64.11 v1(55.88,65.02)
  vias: v1(20.32,36.7) v1(21.34,33.53) v1(22.35,34.8) v1(23.5,33.53) v1(24.64,34.67) v1(25.65,33.53) v1(26.29,35.43) v1(28.07,37.08) v1(29.08,38.1) v1(30.35,36.83) v1(52.2,36.7) v1(53.21,33.53) v1(54.23,34.8) v1(55.37,33.53) v1(56.52,34.67) v1(57.53,33.53) v1(58.17,35.43) v1(59.94,37.08) v1(60.96,38.1) v1(62.23,36.83) v1(63.75,66.04) v1(63.75,64.9) v1(65.02,66.04) v1(65.02,64.9) v1(66.29,64.9) v1(67.56,66.04) v1(67.56,64.9) v1(67.56,63.75) v1(68.83,66.04) v1(68.83,64.9) v1(68.83,63.75) v1(70.1,66.04) v1(70.1,64.9) v1(70.1,63.75) v1(71.37,66.04) v1(71.37,64.9) v1(71.37,63.75) v1(72.64,66.04) v1(72.64,64.9) v1(72.64,63.75) v1(73.91,66.04) v1(73.91,64.9) v1(73.91,63.75) v1(75.18,66.04) v1(75.18,64.9) v1(75.18,63.75) v1(76.33,66.04) v1(76.33,64.9) v1(84.07,36.7) v1(85.09,33.53) v1(86.11,34.8) v1(87.25,33.53) v1(88.39,34.67) v1(89.41,33.53) v1(90.04,35.43) v1(91.82,37.08) v1(92.84,38.1) v1(93.6,39.62) v1(94.11,36.83) v1(94.87,38.99) v1(95.76,38.1) v1(96.14,36.96) v1(97.54,37.72) v1(98.42,39.12)
GND_SIGNAL: length 243.3
  TOP w0.254: C45.1 46.2,46.46 ; C45.1 44.98,46.46 ; C45.1 v1(45.59,45.34) ; v1(8.89,50.55) C38.1 R27.2 ; U1.6 77.03,74.73 v1(76.71,75.06) 77.68,76.03 U1.14 ; v1(8.89,53.59) C35.1 R22.2 ; U1.13 v1(78.33,79.5) ; v1(46.61,46.23) 46.74,46.35 C41.1 ; C14.1 74.3,68.3 74.04,68.05 73.68,68.05 ; R8.2 v1(75.18,67.94) ; 77.28,84.9 R2.2 76.25,84.84 75.95,85.14 v1(75.95,86.11) ; v1(8.89,48.51) C40.1 R28.2 ; C4.1 v1(74.68,82.07) ; C43.1 42.8,46.1 v1(42.93,45.97) ; C15.1 v1(77.09,67.94) ; 73.68,68.05 R10.2 ; 73.68,68.05 v1(73.71,68.02) ; C44.1 v1(44.58,45.97) ; R17.2 50.55,62.74 49.78,62.74 48.88,61.84 48.88,60.97 50.04,59.82 50.04,59.45 R21.2 ; R25.2 C37.1 v1(8.89,51.56) ; R32.2 v1(52.45,48.13) ; v1(49.53,47.5) 49.53,48.12 C46.1 ; R31.2 v1(43.69,45.97) ; J5.6 v1(5.95,54.59) ; C5.1 v1(77.72,82.07) ; R36.2 v1(46.75,45.2)
  TOP w0.305: U4.22 44.63,54.43 v1(44.96,54.1) ; U4.10 46.58,51.28 v1(47.12,51.82)
  TOP w0.381: C29.1 v1(44.58,60.83) ; C36.1 v1(15.24,47.5) ; C28.1 v1(43.56,60.83) ; U3.4 v1(17.21,53.34) ; v1(16.26,53.34) U3.5
  TOP w0.508: C1.1 50.52,98.3 v1(49.66,98.3) ; C1.1 50.57,98.3 v1(51.44,98.3) ; C1.1 v1(50.55,99.19) ; SW1.6 v1(91.19,86.86)
  TOP w0.635: J2.8 3.75,86.46 ; J2.8 1.84,86.46 ; J2.8 2.79,87.42 ; J2.8 2.79,85.51 ; J9.4 88.97,6.11 ; J9.4 88.01,5.15 ; J9.4 89.92,5.15 ; J9.4 88.97,4.19 ; 35.99,95.38 J1.4 36.95,96.33 ; J2.7 3.75,83.96 ; J2.7 2.79,83 ; J2.7 1.84,83.96 ; J2.7 2.79,84.92 ; J8.4 58.05,5.15 ; J8.4 56.13,5.15 ; J8.4 57.09,6.11 ; J8.4 57.09,4.19 ; 1.84,81.46 J2.6 ; J2.6 3.75,81.46 ; J2.6 2.79,82.42 ; J2.6 2.79,80.51 ; J9.3 87.42,5.15 ; J9.3 86.47,4.19 ; J9.3 86.47,6.11 ; 54.59,4.19 J8.3 ; J8.3 55.55,5.15 ; J8.3 54.59,6.11 ; J7.3 23.67,5.15 ; J7.3 22.71,4.19 ; J7.3 22.71,6.11 ; 2.79,79.92 J2.5 1.84,78.96 ; 24.26,5.15 J7.4 ; J7.4 25.21,6.11 ; J7.4 25.21,4.19 ; J7.4 26.17,5.15
  L2_GND w0.635: 2.79,85.51 J2.8 ; J2.8 1.84,86.46 ; J2.8 2.79,87.42 ; J2.8 3.75,86.46 ; J2.6 2.79,82.42 ; J2.6 3.75,81.46 ; J2.6 2.79,80.51 ; J2.6 1.84,81.46 ; J9.3 87.42,5.15 ; J9.3 86.47,4.19 ; J9.3 86.47,6.11 ; J9.3 85.51,5.15 ; J3.2 94.74,73.05 ; J3.2 94.74,71.14 ; J3.2 93.79,72.1 ; J7.4 25.21,6.11 ; J7.4 24.26,5.15 ; J7.4 26.17,5.15 ; J7.4 25.21,4.19 ; 1.84,78.96 J2.5 2.79,79.92 ; H1.5 11.56,56.64 ; H1.5 11.56,54.86 ; H1.5 10.67,55.75 ; H1.5 12.45,55.75 ; J6.2 94.74,52.73 ; J6.2 94.74,50.82 ; J6.2 93.79,51.78 ; 42.91,95.38 J1.2 41.95,94.42 ; 56.13,5.15 J8.4 ; J8.4 57.09,4.19 ; J8.4 58.05,5.15 ; J8.4 57.09,6.11 ; J1.4 36.95,96.33 ; J1.4 35.99,95.38 ; J1.4 37.91,95.38 ; J1.4 36.95,94.42 ; 94.74,60.98 J4.2 ; J4.2 93.79,61.94 ; J4.2 94.74,62.89 ; J9.4 88.97,6.11 ; J9.4 88.01,5.15 ; J9.4 88.97,4.19 ; J9.4 89.92,5.15 ; J7.3 23.67,5.15 ; J7.3 21.76,5.15 ; J7.3 22.71,6.11 ; J7.3 22.71,4.19 ; 1.84,83.96 J2.7 ; J2.7 2.79,84.92 ; J2.7 3.75,83.96 ; J2.7 2.79,83 ; 54.59,4.19 J8.3 ; J8.3 55.55,5.15 ; J8.3 53.63,5.15 ; J8.3 54.59,6.11
  L3_PWR w0.635: J8.4 58.05,5.15 ; J8.4 56.13,5.15 ; J8.4 57.09,4.19 ; J8.4 57.09,6.11 ; J7.4 25.21,6.11 ; J7.4 24.26,5.15 ; J7.4 26.17,5.15 ; J7.4 25.21,4.19 ; 88.01,5.15 J9.4 ; J9.4 88.97,6.11 ; J9.4 89.92,5.15 ; J9.4 88.97,4.19 ; 11.56,54.86 H1.5 ; H1.5 12.45,55.75 ; H1.5 11.56,56.64 ; H1.5 10.67,55.75 ; 93.79,61.94 J4.2 ; J4.2 94.74,62.89 ; J4.2 94.74,60.98 ; 1.84,86.46 J2.8 ; J2.8 2.79,87.42 ; J2.8 3.75,86.46 ; J2.8 2.79,85.51 ; 94.74,50.82 J6.2 ; J6.2 94.74,52.73 ; J6.2 93.79,51.78 ; J2.7 3.75,83.96 ; J2.7 2.79,84.92 ; J2.7 1.84,83.96 ; J2.7 2.79,83 ; J7.3 23.67,5.15 ; J7.3 22.71,6.11 ; J7.3 22.71,4.19 ; J7.3 21.76,5.15 ; J2.6 2.79,82.42 ; J2.6 3.75,81.46 ; J2.6 2.79,80.51 ; J2.6 1.84,81.46 ; 1.84,78.96 J2.5 2.79,79.92 ; J3.2 94.74,73.05 ; J3.2 93.79,72.1 ; J3.2 94.74,71.14 ; 54.59,4.19 J8.3 ; J8.3 55.55,5.15 ; J8.3 54.59,6.11 ; J8.3 53.63,5.15 ; 85.51,5.15 J9.3 ; J9.3 87.42,5.15 ; J9.3 86.47,6.11 ; J9.3 86.47,4.19
  BOTTOM w0.254: v1(75.95,86.11) 75.95,86.61 76.2,86.87 76.83,86.87 77.22,86.49 77.22,83.57 78.61,82.17 78.61,79.78 v1(78.33,79.5)
  BOTTOM w0.635: 1.84,86.46 J2.8 ; J2.8 2.79,85.51 ; J2.8 3.75,86.46 ; J2.8 2.79,87.42 ; J7.4 26.17,5.15 ; J7.4 25.21,6.11 ; J7.4 24.26,5.15 ; J7.4 25.21,4.19 ; J2.7 3.75,83.96 ; J2.7 2.79,83 ; J2.7 2.79,84.92 ; J2.7 1.84,83.96 ; 2.79,79.92 J2.5 1.84,78.96 ; J9.3 86.47,6.11 ; J9.3 86.47,4.19 ; J9.3 87.42,5.15 ; 54.59,4.19 J8.3 ; J8.3 55.55,5.15 ; J8.3 54.59,6.11 ; J9.4 88.97,6.11 ; J9.4 89.92,5.15 ; J9.4 88.97,4.19 ; J9.4 88.01,5.15 ; J4.2 94.74,62.89 ; J4.2 93.79,61.94 ; J4.2 94.74,60.98 ; 94.74,50.82 J6.2 ; J6.2 93.79,51.78 ; J6.2 94.74,52.73 ; J8.4 58.05,5.15 ; J8.4 56.13,5.15 ; J8.4 57.09,4.19 ; J8.4 57.09,6.11 ; J3.2 94.74,73.05 ; J3.2 93.79,72.1 ; J3.2 94.74,71.14 ; 2.79,80.51 J2.6 ; J2.6 3.75,81.46 ; J2.6 1.84,81.46 ; J2.6 2.79,82.42 ; J7.3 22.71,6.11 ; J7.3 22.71,4.19 ; J7.3 23.67,5.15
  vias: v1(1.27,64.14) v1(1.91,44.32) v1(1.91,28.19) v1(2.03,14.1) v1(3.56,20.32) v1(3.81,36.58) v1(4.45,64.14) v1(5.08,86.49) v1(5.08,85.09) v1(5.08,83.69) v1(5.08,82.3) v1(5.08,80.9) v1(5.08,79.5) v1(6.6,86.49) v1(6.6,85.09) v1(6.6,83.69) v1(6.6,82.3) v1(6.6,80.9) v1(6.6,79.5) v1(7.62,93.98) v1(8,95.5) v1(9.27,95.5) v1(9.4,2.16) v1(10.67,2.16) v1(11.81,38.1) v1(11.81,36.32) v1(12.06,2.16) v1(13.72,29.59) v1(13.84,39.88) v1(13.84,38.1) v1(14.48,1.78) v1(15.11,36.83) v1(15.11,35.31) v1(15.24,38.73) v1(15.49,41.27) v1(15.62,32.13) v1(15.62,30.99) v1(16.51,32.13) v1(16.51,30.99) v1(16.64,40.13) v1(16.89,36.83) v1(17.02,42.67) v1(17.14,38.48) v1(17.78,1.78) v1(18.03,41.4) v1(18.41,39.62) v1(19.68,40.89) v1(19.94,42.55) v1(20.95,39.62) v1(22.48,42.93) v1(23.11,1.78) v1(23.37,13.97) v1(23.88,42.04) v1(23.88,12.95) v1(23.88,7.75) v1(23.88,3.05) v1(24.64,6.48) v1(24.89,1.91) v1(25.78,58.78) v1(25.78,57.4) v1(25.78,55.98) v1(25.78,54.61) v1(25.78,11.43) v1(25.78,9.4) v1(25.78,7.75) v1(25.78,3.05) v1(26.67,6.48) v1(26.67,4.19) v1(26.67,1.91) v1(26.8,10.67) v1(26.8,8.76) v1(27.18,58.78) v1(27.18,57.4) v1(27.18,55.98) v1(27.18,54.61) v1(27.69,11.43) v1(27.69,9.65) v1(27.69,7.75) v1(27.69,5.33) v1(27.69,3.05) v1(28.57,58.78) v1(28.57,57.4) v1(28.57,55.98) v1(28.57,54.61) v1(28.57,6.48) v1(28.57,4.19) v1(28.57,1.91) v1(28.7,10.67) v1(28.7,8.76) v1(29.59,11.43) v1(29.59,9.65) v1(29.59,7.75) v1(29.59,5.33) v1(29.59,3.05) v1(30.48,6.48) v1(30.48,4.19) v1(30.48,1.91) v1(30.61,10.67) v1(30.61,8.76) v1(31.5,11.94) v1(31.5,9.65) v1(31.5,7.75) v1(31.5,5.33) v1(31.5,3.05) v1(32.38,6.48) v1(32.38,4.19) v1(32.38,1.91) v1(32.51,12.95) v1(32.51,10.67) v1(32.51,8.76) v1(33.27,96.14) v1(33.4,11.81) v1(33.4,9.65) v1(33.4,7.75) v1(33.4,5.33) v1(33.4,3.05) v1(34.04,97.28) v1(34.8,96.27) v1(34.8,59.41) v1(34.8,58.04) v1(34.8,56.62) v1(34.8,55.24) v1(34.8,53.59) v1(36.2,59.41) v1(36.2,58.04) v1(36.2,56.62) v1(36.2,55.24) v1(36.2,53.59) v1(37.21,52.07) v1(37.59,58.04) v1(37.59,56.62) v1(37.59,55.24) v1(37.59,53.59) v1(38.23,51.31) v1(39.24,52.2) v1(41.27,2.16) v1(42.55,2.16) v1(42.67,54.1) v1(42.67,52.96) v1(42.67,51.82) v1(42.93,41.15) v1(43.69,38.1) v1(43.69,36.32) v1(43.81,54.1) v1(43.81,52.96) v1(43.81,51.82) v1(43.94,2.16) v1(44.7,42.93) v1(44.96,52.96) v1(44.96,51.82) v1(45.47,29.59) v1(45.72,39.62) v1(46.1,54.1) v1(46.1,52.96) v1(46.1,51.82) v1(46.23,1.91) v1(46.74,38.23) v1(46.99,36.83) v1(46.99,35.31) v1(47.12,54.1) v1(47.12,52.96) v1(47.37,41.15) v1(47.5,32.13) v1(47.5,30.99) v1(48.26,39.88) v1(48.39,32.13) v1(48.39,30.99) v1(48.77,36.83) v1(48.9,42.55) v1(49.02,38.35) v1(49.53,1.91) v1(49.78,41.15) v1(50.29,39.62) v1(51.56,40.89) v1(51.82,42.67) v1(52.32,59.44) v1(52.32,58.04) v1(52.32,56.64) v1(52.32,55.24) v1(52.32,53.85) v1(52.32,52.45) v1(53.34,40.01) v1(53.85,59.44) v1(53.85,58.04) v1(53.85,56.64) v1(53.85,55.24) v1(53.85,53.85) v1(53.85,52.45) v1(53.98,49.53) v1(53.98,46.35) v1(53.98,42.67) v1(54.99,1.78) v1(55.24,13.97) v1(55.37,59.44) v1(55.37,58.04) v1(55.37,56.64) v1(55.37,55.24) v1(55.37,53.85) v1(55.37,52.45) v1(55.75,12.95) v1(55.75,7.75) v1(55.75,3.05) v1(56.26,42.42) v1(56.52,6.48) v1(56.77,1.91) v1(56.9,59.44) v1(56.9,58.04) v1(56.9,56.64) v1(56.9,55.24) v1(56.9,53.85) v1(56.9,52.45) v1(57.15,49.53) v1(57.15,46.35) v1(57.66,11.43) v1(57.66,9.4) v1(57.66,7.75) v1(57.66,3.05) v1(58.42,59.44) v1(58.42,58.04) v1(58.42,56.64) v1(58.42,55.24) v1(58.42,53.85) v1(58.42,52.45) v1(58.55,6.48) v1(58.55,4.19) v1(58.55,1.91) v1(58.67,10.67) v1(58.67,8.76) v1(59.56,11.43) v1(59.56,9.65) v1(59.56,7.75) v1(59.56,5.33) v1(59.56,3.05) v1(59.94,59.44) v1(59.94,58.04) v1(59.94,56.64) v1(59.94,55.24) v1(59.94,53.85) v1(59.94,52.45) v1(60.33,49.53) v1(60.33,46.35) v1(60.45,6.48) v1(60.45,4.19) v1(60.45,1.91) v1(60.58,10.67) v1(60.58,8.76) v1(61.47,59.44) v1(61.47,58.04) v1(61.47,56.64) v1(61.47,55.24) v1(61.47,53.85) v1(61.47,52.45) v1(61.47,11.43) v1(61.47,9.65) v1(61.47,7.75) v1(61.47,5.33) v1(61.47,3.05) v1(62.36,6.48) v1(62.36,4.19) v1(62.36,1.91) v1(62.48,10.67) v1(62.48,8.76) v1(63.37,11.94) v1(63.37,9.65) v1(63.37,7.75) v1(63.37,5.33) v1(63.37,3.05) v1(63.5,49.53) v1(63.5,46.35) v1(64.26,6.48) v1(64.26,4.19) v1(64.26,1.91) v1(64.39,12.95) v1(64.39,10.67) v1(64.39,8.76) v1(65.28,11.81) v1(65.28,9.65) v1(65.28,7.75) v1(65.28,5.33) v1(65.28,3.05) v1(65.66,53.85) v1(65.66,52.45) v1(66.67,49.53) v1(66.67,46.35) v1(67.18,53.85) v1(67.18,52.45) v1(68.71,53.85) v1(68.71,52.45) v1(69.85,49.53) v1(69.85,46.35) v1(69.85,43.18) v1(70.23,53.85) v1(70.23,52.45) v1(71.75,53.85) v1(71.75,52.45) v1(71.88,79.38) v1(71.88,77.72) v1(72.14,75.95) v1(72.14,74.3) v1(73.03,49.53) v1(73.03,46.35) v1(73.03,43.18) v1(73.15,2.16) v1(73.28,53.85) v1(73.28,52.45) v1(73.32,39.71) v1(73.66,75.95) v1(73.66,74.3) v1(74.42,2.16) v1(74.8,53.85) v1(74.8,52.45) v1(75.18,75.95) v1(75.18,74.3) v1(75.56,38.1) v1(75.56,36.32) v1(75.82,2.16) v1(76.2,49.53) v1(76.2,46.35) v1(77.34,39.62) v1(77.34,37.59) v1(77.47,43.18) v1(77.47,29.72) v1(77.6,1.65) v1(78.23,75.95) v1(78.23,74.3) v1(78.36,66.8) v1(78.61,86.74) v1(78.61,85.34) v1(78.61,84.07) v1(78.74,41.02) v1(78.87,36.83) v1(78.87,35.31) v1(79.12,55.63) v1(79.25,64.77) v1(79.25,63.5) v1(79.25,60.71) v1(79.25,59.31) v1(79.25,39.12) v1(79.38,49.53) v1(79.38,46.35) v1(79.38,32.13) v1(79.38,30.99) v1(79.5,67.26) v1(79.63,51.18) v1(79.76,75.95) v1(79.76,74.3) v1(79.88,86.74) v1(79.88,85.34) v1(79.88,84.07) v1(80.14,42.42) v1(80.26,32.13) v1(80.26,30.99) v1(80.64,36.83) v1(80.77,64.77) v1(80.77,63.5) v1(80.77,60.71) v1(80.77,59.31) v1(80.77,38.23) v1(80.9,40.77) v1(80.9,1.65) v1(81.15,86.74) v1(81.15,85.34) v1(81.15,84.07) v1(81.28,75.95) v1(81.28,74.3) v1(81.28,43.69) v1(82.17,39.62) v1(82.3,44.96) v1(82.55,49.53) v1(82.8,56.52) v1(82.93,51.18) v1(83.06,42.8) v1(83.44,40.89) v1(84.58,45.47) v1(84.71,39.75) v1(85.98,43.43) v1(86.87,1.78) v1(87.12,13.97) v1(87.63,12.95) v1(87.63,7.75) v1(87.63,3.05) v1(88.01,42.42) v1(88.39,6.48) v1(88.65,45.47) v1(88.65,1.91) v1(89.53,11.43) v1(89.53,9.4) v1(89.53,7.75) v1(89.53,3.05) v1(90.17,43.43) v1(90.42,6.48) v1(90.42,4.19) v1(90.42,1.91) v1(90.55,10.67) v1(90.55,8.76) v1(91.44,11.43) v1(91.44,9.65) v1(91.44,7.75) v1(91.44,5.33) v1(91.44,3.05) v1(92.33,6.48) v1(92.33,4.19) v1(92.33,1.91) v1(92.46,10.67) v1(92.46,8.76) v1(92.96,45.72) v1(93.34,11.43) v1(93.34,9.65) v1(93.34,7.75) v1(94.36,10.67) v1(95.25,11.94) v1(95.25,7.75) v1(95.5,44.45) v1(96.27,12.95) v1(97.16,11.81) v1(97.16,7.75)
VBATT: length 40.2
  TOP w0.635: 2.79,68 J2.1 ; J2.1 1.84,68.96 ; J2.1 2.79,69.92 ; J2.1 3.75,68.96 ; 1.84,76.46 J2.4 2.79,75.51 ; J2.3 2.79,74.92 ; J2.3 1.84,73.96 ; J2.3 3.75,73.96 ; J2.3 2.79,73 ; 1.84,71.46 J2.2 ; J2.2 2.79,72.42 ; J2.2 2.79,70.51 ; J2.2 3.75,71.46
  L3_PWR w0.635: 1.84,76.46 J2.4 2.79,75.51 ; J2.2 2.79,72.42 ; J2.2 2.79,70.51 ; J2.2 1.84,71.46 ; J2.2 3.75,71.46 ; J2.3 3.75,73.96 ; J2.3 2.79,74.92 ; J2.3 2.79,73 ; J2.3 1.84,73.96 ; 2.79,68 J2.1 ; J2.1 2.79,69.92 ; J2.1 1.84,68.96 ; J2.1 3.75,68.96
  BOTTOM w0.635: J2.1 2.79,69.92 ; J2.1 3.75,68.96 ; J2.1 1.84,68.96 ; J2.1 2.79,68 ; J2.2 3.75,71.46 ; J2.2 2.79,72.42 ; J2.2 2.79,70.51 ; J2.2 1.84,71.46 ; J2.3 3.75,73.96 ; J2.3 2.79,74.92 ; J2.3 1.84,73.96 ; J2.3 2.79,73 ; 1.84,76.46 J2.4 2.79,75.51
  vias: v1(8.51,71.88) v1(8.51,70.48) v1(8.51,69.09) v1(8.51,67.69) v1(8.51,66.29) v1(10.03,71.88) v1(10.03,70.48) v1(10.03,69.09) v1(10.03,67.69) v1(10.03,66.29) v1(11.56,71.88) v1(11.56,70.48) v1(11.56,69.09) v1(11.56,67.69) v1(11.56,66.29) v1(13.08,71.88) v1(13.08,70.48) v1(13.08,69.09) v1(13.08,67.69) v1(13.08,66.29)
VCC: length 39.7
  TOP w0.254: v1(42.04,48.02) 42.04,48.27 42.68,48.92 U4.4
  TOP w0.305: v1(44.32,57.02) 43.98,56.68 U4.23
  TOP w0.381: v1(44.32,57.02) 44.58,57.28 C29.2
  TOP w0.508: R18.1 47,60.31 v1(47,61.48) 46.96,61.44 D8.A 45.69,61.59 41.3,61.59 D7.A
  BOTTOM w0.254: v1(42.04,48.02) 43.8,49.78 49.66,49.78 50.8,50.93 50.8,54.86 49.53,56.13 45.21,56.13 v1(44.32,57.02)
  BOTTOM w0.508: v1(47,61.48) 44.32,58.8 v1(44.32,57.02)
VIN_HEATER: length 5.7
  TOP w0.635: J1.1 44.45,96.33 ; J1.1 45.41,95.38 ; J1.1 44.45,94.42
  BOTTOM w0.635: J1.1 45.41,95.38 ; J1.1 44.45,96.33 ; J1.1 44.45,94.42
  vias: v1(45.21,93.34) v1(46.86,96.27) v1(46.86,94.87) v1(46.86,93.34) v1(48.26,96.27) v1(48.26,94.87)
VIN_MAIN: length 4.2
  TOP w1.27: J1.3 39.45,93.3
  BOTTOM w1.27: J1.3 39.45,93.3
  vias: v1(32.26,91.69) v1(32.26,90.3) v1(33.91,91.69) v1(33.91,90.3) v1(35.56,91.69) v1(35.56,90.3) v1(37.21,91.69) v1(37.21,90.3)
CSN: length 3.1
  TOP w0.254: U4.15 49.18,56.64 49.44,56.9 49.8,56.9 50.18,57.28 C34.1 50.18,58.27 R21.1
CSP: length 2.8
  TOP w0.254: R20.1 49.14,58.14 C34.2 48.53,56.93 U4.16
FB: length 5.9
  TOP w0.254: R33.2 R32.1 50.41,48.54 v1(50.04,48.91) ; U4.11 v1(47.23,48.91)
  BOTTOM w0.254: v1(47.23,48.91) v1(50.04,48.91)
HDRV1: length 19.3
  TOP w0.254: U4.27 41.38,56.79 v1(41.02,57.15) ; R5.1 v1(32.77,70.74)
  BOTTOM w0.254: v1(41.02,57.15) 38.8,59.37 38.8,61.4 38.23,61.98 38.23,65.28 v1(32.77,70.74)
HDRV2: length 16.4
  TOP w0.254: v1(46.65,57.15) 46.58,57.07 U4.19 ; R12.1 v1(54.36,66.8)
  BOTTOM w0.254: v1(54.36,66.8) 54.36,63.37 48.22,57.23 v1(46.65,57.15)
LDRV1: length 13.4
  TOP w0.254: R14.1 v1(41.66,66.55) ; U4.25 v1(42.68,57.4)
  BOTTOM w0.254: v1(41.66,66.55) 43.31,64.9 43.31,62.61 41.4,60.71 41.4,58.68 v1(42.68,57.4)
LDRV2: length 14.7
  TOP w0.254: R16.1 53.07,65.02 v1(51.94,65.02) ; U4.21 v1(45.28,57.08)
  BOTTOM w0.254: v1(45.28,57.08) 45.28,58.62 47.12,60.45 49.66,60.45 51.94,62.74 v1(51.94,65.02)
LO: length 3
  TOP w0.254: R3.1 77.72,79.88 77.03,79.19 U1.15
P6P5V: length 1.5
  TOP w0.508: J5.5 v1(3.3,53.59)
PMIC_LEDSEL_0: length 29.9
  TOP w0.254: v1(12.53,31.68) 12.64,31.57 U5.3 ; J5.1 5.4,49.59 6.48,48.51 C40.2 R28.1 7.1,46.37 7.87,45.59 H1.1
  BOTTOM w0.254: v1(12.53,31.68) 9.34,31.68 8.13,32.89 8.13,42.16 H1.1
PMIC_LEDSEL_1: length 50.6
  TOP w0.254: H1.2 13.46,48.13 17.02,44.58 25.4,44.58 35.81,34.16 v1(38.23,34.16) ; v1(44.32,31.75) 44.5,31.57 U6.3 ; J5.2 v1(6.22,50.59) 7.05,50.59 C38.2 R27.1
  BOTTOM w0.254: v1(44.32,31.75) 40.64,31.75 v1(38.23,34.16) ; H1.2 10.41,49.28 7.54,49.28 v1(6.22,50.59)
PMIC_LEDSEL_2: length 87.4
  TOP w0.254: H1.3 10.03,49.15 10.03,47.62 10.79,46.86 13.34,46.86 v1(15.49,44.7) ; R25.1 C37.2 7.07,51.59 v1(6.22,51.59) J5.3 ; v1(76.2,31.75) 76.38,31.57 U7.3
  BOTTOM w0.254: v1(76.2,31.75) 72.52,31.75 60.71,43.56 16.64,43.56 v1(15.49,44.7) ; H1.3 10.79,49.91 7.91,49.91 v1(6.22,51.59)
PMIC_LEDSEL_3: length 13.8
  TOP w0.254: U3.6 13.04,54.7 H1.4 ; R22.1 C35.2 v1(6.29,53.02) 5.86,52.59 J5.4
  BOTTOM w0.254: H1.4 10.03,53.21 9.4,52.58 6.73,52.58 v1(6.29,53.02)
PWM0_OUT_F: length 32
  TOP w0.254: R47.1 9.3,35.03 v1(9.27,35.05) ; L8.2 9.14,55.63 9.65,56.13 9.65,57.66 10.29,58.29 11.56,58.29
  BOTTOM w0.254: v1(9.27,35.05) 9.27,40.01 13.08,43.81 13.08,56.77 11.56,58.29
PWM1_OUT_F: length 49.8
  TOP w0.254: R48.1 39.94,35.05 35.94,35.05 25.4,45.59 24.38,45.59 18.1,51.88 18.1,55.69 12.95,60.83 9.65,60.83 8.89,60.07 8.89,57.02 8.51,56.64 L7.2
PWM2_OUT_F: length 84
  TOP w0.254: R49.1 72.89,33.91 v1(71.37,33.91) ; L6.2 8.14,61.48 10.03,63.37 11.56,63.37 18.73,56.2 18.73,52.13 24.38,46.48 25.65,46.48 v1(27.94,44.2)
  BOTTOM w0.254: v1(27.94,44.2) 61.09,44.2 v1(71.37,33.91)
SHUNT_EN: length 180.3
  TOP w0.254: R24.2 R23.2 v1(16.26,46.99) TP4.1 ; v1(46.1,3.68) 45.16,3.68 Q12.4 ; Q11.4 13.29,3.68 v1(13.97,3.68) ; Q13.4 v1(77.8,3.76)
  BOTTOM w0.254: 16,34.04 12.57,30.61 7.37,30.61 5.71,28.96 5.71,8.26 10.29,3.68 v1(13.97,3.68) ; 16,34.04 18.29,31.75 36.07,31.75 37.34,30.48 ; 16,34.04 16,39.24 14.73,40.51 14.73,45.47 v1(16.26,46.99) ; 37.34,30.48 46.35,30.48 46.86,29.97 49.28,29.97 49.78,30.48 57.91,30.48 69.6,18.8 69.6,7.49 73.33,3.76 v1(77.8,3.76) ; 37.34,30.48 37.34,7.49 41.15,3.68 v1(46.1,3.68)
SW1: length 15.1
  TOP w0.254: v1(39.6,59.56) C33.1 39.6,56.29 40.13,55.76 U4.28
  BOTTOM w0.254: v1(37.34,69.09) 38.99,67.44 38.99,62.74 39.6,62.13 v1(39.6,59.56)
  vias: v1(32.38,74.42) v1(32.38,73.03) v1(33.53,74.42) v1(33.53,73.03) v1(34.67,74.42) v1(34.67,73.03) v1(34.67,71.75) v1(34.67,70.48) v1(36.2,73.15) v1(36.2,71.75) v1(36.2,70.48) v1(37.34,73.15) v1(37.72,71.75) v1(38.48,73.15) v1(39.24,71.75) v1(40.01,73.15) v1(40.64,71.75) v1(41.15,73.15) v1(42.29,73.15)
SW2: length 19.2
  TOP w0.254: v1(47.12,59.05) 47.14,59.05 47.4,58.8 C32.1 47.4,56.92 47.23,56.75 U4.18
  BOTTOM w0.254: v1(47.12,59.05) 49.15,59.05 53.72,63.63 53.72,67.69 54.36,68.33 v1(54.36,70.61)
  vias: v1(50.67,73.28) v1(50.67,71.88) v1(51.82,73.28) v1(51.82,71.88) v1(52.96,73.28) v1(52.96,71.88) v1(54.36,73.28) v1(54.36,71.88) v1(55.5,73.28) v1(55.5,71.88) v1(55.5,70.61) v1(56.64,73.28) v1(56.64,71.88) v1(56.64,70.61) v1(57.91,73.28) v1(57.91,71.88) v1(59.05,73.28) v1(59.05,71.88) v1(60.33,73.28) v1(60.33,71.88) v1(61.47,73.28) v1(61.47,71.88)
V_BATT_PROT: length 26
  TOP w0.254: v1(35.05,49.66) 35.05,45.47 35.69,44.83 40.01,44.83 41.16,45.99 R35.1 41.16,48.27 42.03,49.14 U4.3 ; 71.5,70.35 R7.1 71.02,69.86 ; R9.1 76.07,67.56 75.69,67.18 70.99,67.18 70.36,67.82 70.36,69.98
  vias: v1(19.56,68.07) v1(19.56,66.67) v1(19.56,65.15) v1(19.56,63.75) v1(21.21,68.07) v1(21.21,66.67) v1(21.21,65.15) v1(21.21,63.75) v1(27.05,98.17) v1(27.05,96.77) v1(27.05,95.38) v1(27.3,79.12) v1(27.3,77.72) v1(27.3,76.33) v1(27.3,74.93) v1(27.3,73.28) v1(27.3,71.88) v1(27.3,70.36) v1(27.3,68.96) v1(27.3,67.44) v1(27.3,66.04) v1(28.45,98.17) v1(28.45,96.77) v1(28.45,95.38) v1(28.96,79.12) v1(28.96,77.72) v1(28.96,76.33) v1(28.96,74.93) v1(28.96,73.28) v1(28.96,71.88) v1(28.96,70.36) v1(28.96,68.96) v1(28.96,67.44) v1(28.96,66.04) v1(29.84,98.17) v1(29.84,96.77) v1(29.84,95.38) v1(30.99,67.69) v1(30.99,66.42) v1(30.99,65.28) v1(31.24,98.17) v1(31.24,96.77) v1(32.77,67.69) v1(32.77,66.42) v1(32.77,65.28) v1(34.04,49.66) v1(34.16,50.55) v1(35.05,50.55) v1(52.7,97.16) v1(52.7,92.58) v1(54.36,97.16) v1(54.36,95.76) v1(54.36,94.23) v1(54.36,92.58) v1(62.36,92.71) v1(62.36,91.44) v1(63.75,92.71) v1(63.75,91.44) v1(64.77,73.79) v1(64.77,72.52) v1(64.77,71.12) v1(65.15,92.71) v1(65.15,91.44) v1(66.17,73.79) v1(66.17,72.52) v1(66.17,71.12) v1(67.56,73.79) v1(67.56,72.52) v1(67.56,71.12) v1(68.96,72.52) v1(68.96,71.12) v1(70.36,72.52) v1(70.36,71.12) v1(71.75,72.52) v1(71.75,71.12)
V_FAN: length 10
  TOP w0.381: U1.10 79.63,72.26 80.39,72.26
  TOP w0.508: 82.55,72.26 80.39,72.26 ; R11.1 83.77,70.1
  TOP w1.524: J3.1 93.09,69.6 ; J6.1 92.84,49.28 ; J4.1 92.84,59.44
V_LED_0: length 16
  TOP w0.508: R55.2 73.81,28.35
  TOP w0.635: J9.1 81.47,6.11 ; J9.1 82.42,5.15 ; J9.1 80.51,5.15 ; 83.01,5.15 J9.2 83.97,6.11
  L3_PWR w0.635: 83.01,5.15 J9.2 83.97,6.11 ; J9.1 81.47,6.11 ; J9.1 80.51,5.15 ; J9.1 82.42,5.15
  BOTTOM w0.635: 83.97,6.11 J9.2 83.01,5.15 ; 80.51,5.15 J9.1 ; J9.1 82.42,5.15 ; J9.1 81.47,6.11
  vias: v1(70.87,27.69) v1(70.87,25.15) v1(70.87,23.11) v1(70.87,20.83) v1(70.87,18.29) v1(71.63,26.42) v1(72.14,9.65) v1(72.14,8.38) v1(72.39,18.29) v1(72.39,16.76) v1(72.39,14.99) v1(72.64,27.69) v1(72.64,25.15) v1(73.41,26.42) v1(73.91,11.18) v1(74.09,5.18) v1(74.17,27.69) v1(74.17,25.15) v1(74.17,18.29) v1(74.17,16.76) v1(74.17,14.99) v1(75.18,26.42) v1(75.69,11.18) v1(75.95,27.69) v1(75.95,25.15) v1(75.95,23.11) v1(75.95,20.83) v1(75.95,18.29) v1(75.95,16.76) v1(75.95,14.99) v1(75.87,5.18) v1(77.47,5.59) v1(77.72,14.48) v1(77.72,12.95) v1(77.72,11.43) v1(78.23,9.65) v1(78.23,8.38) v1(78.99,7.11) v1(79.25,5.59) v1(79.5,14.48) v1(79.5,12.95) v1(79.5,11.43) v1(79.5,9.91) v1(79.5,8.38) v1(80.77,7.11) v1(81.28,14.48) v1(81.28,12.95) v1(81.28,11.43) v1(81.28,9.91) v1(81.28,8.38) v1(82.55,7.11) v1(82.8,14.48) v1(82.8,12.95) v1(83.06,8.38) v1(84.07,7.11) v1(84.58,14.86)
V_LED_1: length 16.4
  TOP w0.508: R53.2 10.57,28.02
  TOP w0.635: J7.1 17.71,6.11 ; J7.1 16.76,5.15 ; J7.1 18.67,5.15 ; 20.21,6.11 J7.2 19.26,5.15
  L3_PWR w0.635: 16.76,5.15 J7.1 ; J7.1 17.71,6.11 ; J7.1 18.67,5.15 ; 20.21,6.11 J7.2 19.26,5.15
  BOTTOM w0.635: J7.1 17.71,6.11 ; J7.1 18.67,5.15 ; J7.1 16.76,5.15 ; 20.21,6.11 J7.2 19.26,5.15
  vias: v1(7.11,27.69) v1(7.11,25.15) v1(7.11,23.11) v1(7.11,20.83) v1(7.11,18.29) v1(7.87,26.42) v1(8.38,9.65) v1(8.38,8.38) v1(8.64,18.29) v1(8.64,16.76) v1(8.64,14.99) v1(8.89,27.69) v1(8.89,25.15) v1(9.65,26.42) v1(10.16,11.18) v1(10.41,27.69) v1(10.41,25.15) v1(10.41,18.29) v1(10.41,16.76) v1(10.41,14.99) v1(10.59,5.18) v1(11.43,26.42) v1(11.94,11.18) v1(12.19,27.69) v1(12.19,25.15) v1(12.19,23.11) v1(12.19,20.83) v1(12.19,18.29) v1(12.19,16.76) v1(12.19,14.99) v1(12.37,5.18) v1(13.72,14.48) v1(13.72,12.95) v1(13.72,11.43) v1(13.72,5.59) v1(14.22,9.65) v1(14.22,8.38) v1(14.99,7.11) v1(15.49,14.48) v1(15.49,12.95) v1(15.49,11.43) v1(15.49,9.91) v1(15.49,8.38) v1(15.49,5.59) v1(16.76,7.11) v1(17.27,14.48) v1(17.27,12.95) v1(17.27,11.43) v1(17.27,9.91) v1(17.27,8.38) v1(18.54,7.11) v1(18.8,14.48) v1(18.8,12.95) v1(19.05,8.38) v1(20.07,7.11) v1(20.57,14.86)
V_LED_2: length 16.6
  TOP w0.508: 42.44,28.02 42.44,29.15 41.94,29.65 R54.2
  TOP w0.635: J8.1 50.55,5.15 ; J8.1 49.59,6.11 ; J8.1 48.63,5.15 ; 51.13,5.15 J8.2 52.09,6.11
  L3_PWR w0.635: J8.1 49.59,6.11 ; J8.1 50.55,5.15 ; J8.1 48.63,5.15 ; 51.13,5.15 J8.2 52.09,6.11
  BOTTOM w0.635: 51.13,5.15 J8.2 52.09,6.11 ; 48.63,5.15 J8.1 ; J8.1 50.55,5.15 ; J8.1 49.59,6.11
  vias: v1(39.12,27.43) v1(39.12,24.89) v1(39.12,22.86) v1(39.12,20.57) v1(39.12,18.03) v1(39.88,26.16) v1(40.13,9.65) v1(40.13,8.38) v1(40.64,18.03) v1(40.64,16.51) v1(40.64,14.73) v1(40.89,27.43) v1(40.89,24.89) v1(41.66,26.16) v1(41.91,11.18) v1(42.34,5.18) v1(42.42,27.43) v1(42.42,24.89) v1(42.42,18.03) v1(42.42,16.51) v1(42.42,14.73) v1(43.43,26.16) v1(43.69,11.18) v1(44.12,5.18) v1(44.2,27.43) v1(44.2,24.89) v1(44.2,22.86) v1(44.2,20.57) v1(44.2,18.03) v1(44.2,16.51) v1(44.2,14.73) v1(45.72,14.48) v1(45.72,12.95) v1(45.72,11.43) v1(45.72,5.59) v1(46.23,9.65) v1(46.23,8.38) v1(46.99,7.11) v1(47.5,14.48) v1(47.5,12.95) v1(47.5,11.43) v1(47.5,9.91) v1(47.5,8.38) v1(47.5,5.59) v1(48.77,7.11) v1(49.28,14.48) v1(49.28,12.95) v1(49.28,11.43) v1(49.28,9.91) v1(49.28,8.38) v1(50.55,7.11) v1(50.8,14.48) v1(50.8,12.95) v1(51.05,8.38) v1(52.07,7.11) v1(52.58,14.86)
N56946: length 2.3
  TOP w0.254: R38.1 13.67,33.74 R41.2 13.67,33.72 U5.1
N57442: length 3.1
  TOP w0.254: U5.4 13.65,31.05 12.8,31.05 12.79,31.05 12.27,31.05 12.26,31.05 11.83,31.05 C60.2 R53.1
N57562: length 1.5
  TOP w0.254: U5.9 19.44,32.07 19.56,32.19 C57.1
N57763: length 15.8
  TOP w0.254: R50.1 31.04,32.26 30.1,32.26 28.14,30.3 24.69,30.3 23.92,31.07 U5.7
  vias: v1(32.38,28.45) v1(33.53,29.84) v1(33.53,28.45) v1(34.67,29.84) v1(34.67,28.45)
N57852: length 1.5
  TOP w0.254: R56.1 19.56,30.44 19.43,30.57 19.13,30.57 19.12,30.57 U5.6
N60750: length 2.3
  TOP w0.254: R39.1 45.54,33.74 R42.2 45.54,33.72 U6.1
N60866: length 3.6
  TOP w0.254: R54.1 C61.2 44.12,31.08 44.14,31.05 44.85,31.05 44.87,31.07 U6.4
N60906: length 1.5
  TOP w0.254: C58.1 51.69,32.07 U6.9
N60948: length 15.8
  TOP w0.254: R51.1 62.92,32.26 61.98,32.26 60.02,30.3 56.57,30.3 55.8,31.07 U6.7
  vias: v1(64.26,28.45) v1(65.41,29.72) v1(65.41,28.45) v1(66.55,29.72) v1(66.55,28.45)
N61008: length 1.5
  TOP w0.254: U6.6 50.83,30.57 50.97,30.44 R57.1
N64164: length 2.3
  TOP w0.254: R40.1 77.42,33.74 R43.2 77.42,33.72 U7.1
N64276: length 3.6
  TOP w0.254: R55.1 C62.2 75.57,31.07 U7.4
N64324: length 1.5
  TOP w0.254: C59.1 83.31,32.19 83.19,32.07 U7.9
N64418: length 15.8
  TOP w0.254: U7.7 87.67,31.07 88.44,30.3 91.9,30.3 93.85,32.26 94.79,32.26 R52.1
  vias: v1(96.27,28.45) v1(97.41,29.59) v1(97.41,28.45) v1(98.42,29.59) v1(98.42,28.45)
N64426: length 1.5
  TOP w0.254: U7.6 82.88,30.57 82.88,30.57 83.19,30.57 83.31,30.44 R58.1
N66768: length 4.3
  TOP w0.254: 40.64,48.79 40.97,48.79 41.38,49.21 U4.2
  TOP w0.508: 39.37,48.79 40.64,48.79
  TOP w0.762: C39.2 39.37,48.79
N67488: length 2.2
  TOP w0.254: U4.7 44.63,48.07 C44.2
N67495: length 2.4
  TOP w0.254: U4.5 43.33,48.92 42.8,48.39 C43.2
N67553: length 5.4
  TOP w0.254: R35.2 40.13,47 v1(40.13,47.75) ; v1(39.24,49.78) R26.1 39.89,50.41 40.13,50.16 U4.1
  BOTTOM w0.254: v1(40.13,47.75) 40.13,48.9 v1(39.24,49.78)
N67657: length 3.7
  TOP w0.254: R18.2 48.26,59.05 48.26,57.53 47.88,57.15 U4.17
N68022: length 3.2
  TOP w0.254: C42.2 C41.2 46.74,48.26 45.93,49.06 U4.9
N68052: length 0.9
  TOP w0.254: R36.1 C42.1
